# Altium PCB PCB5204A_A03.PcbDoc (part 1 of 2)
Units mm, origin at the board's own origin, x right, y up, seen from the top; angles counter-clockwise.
Board outline 38.5 x 55.5 mm, 4 copper layers (Top Layer, Signal Layer 2, Signal Layer 3, Bottom Layer), stack 1.6 mm thick; 164 components, 105 nets, 579 pads, 390 vias.
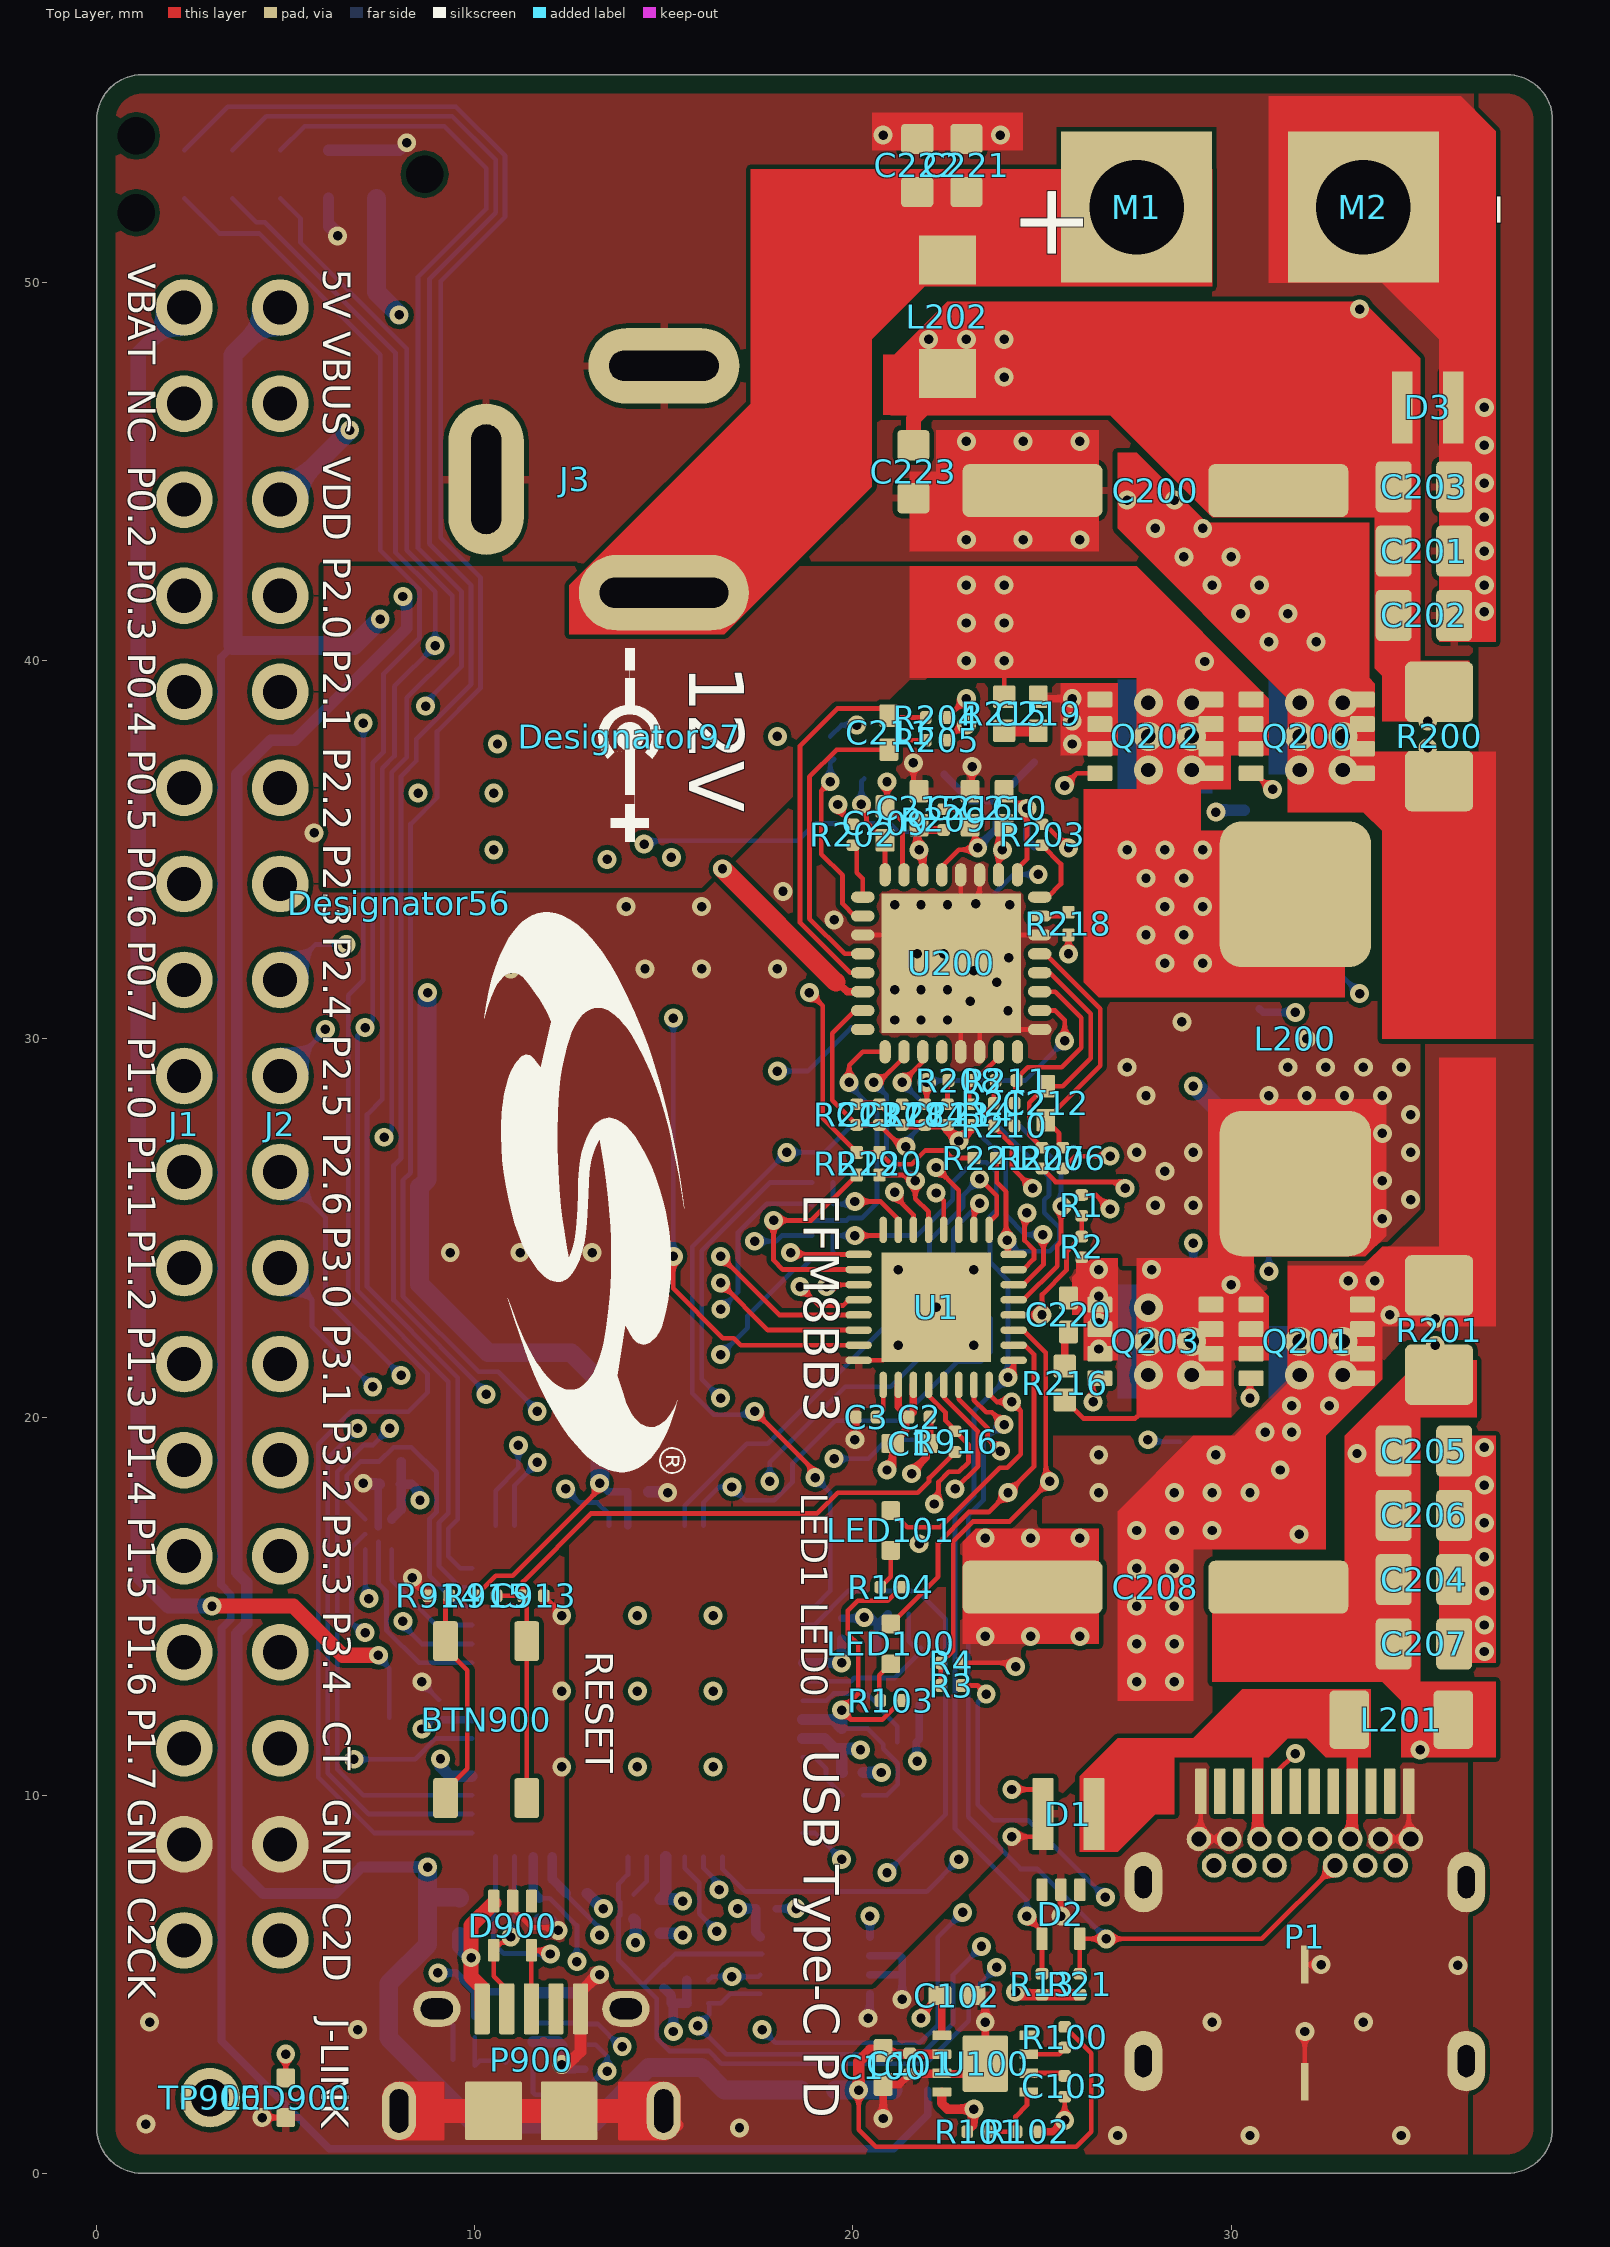
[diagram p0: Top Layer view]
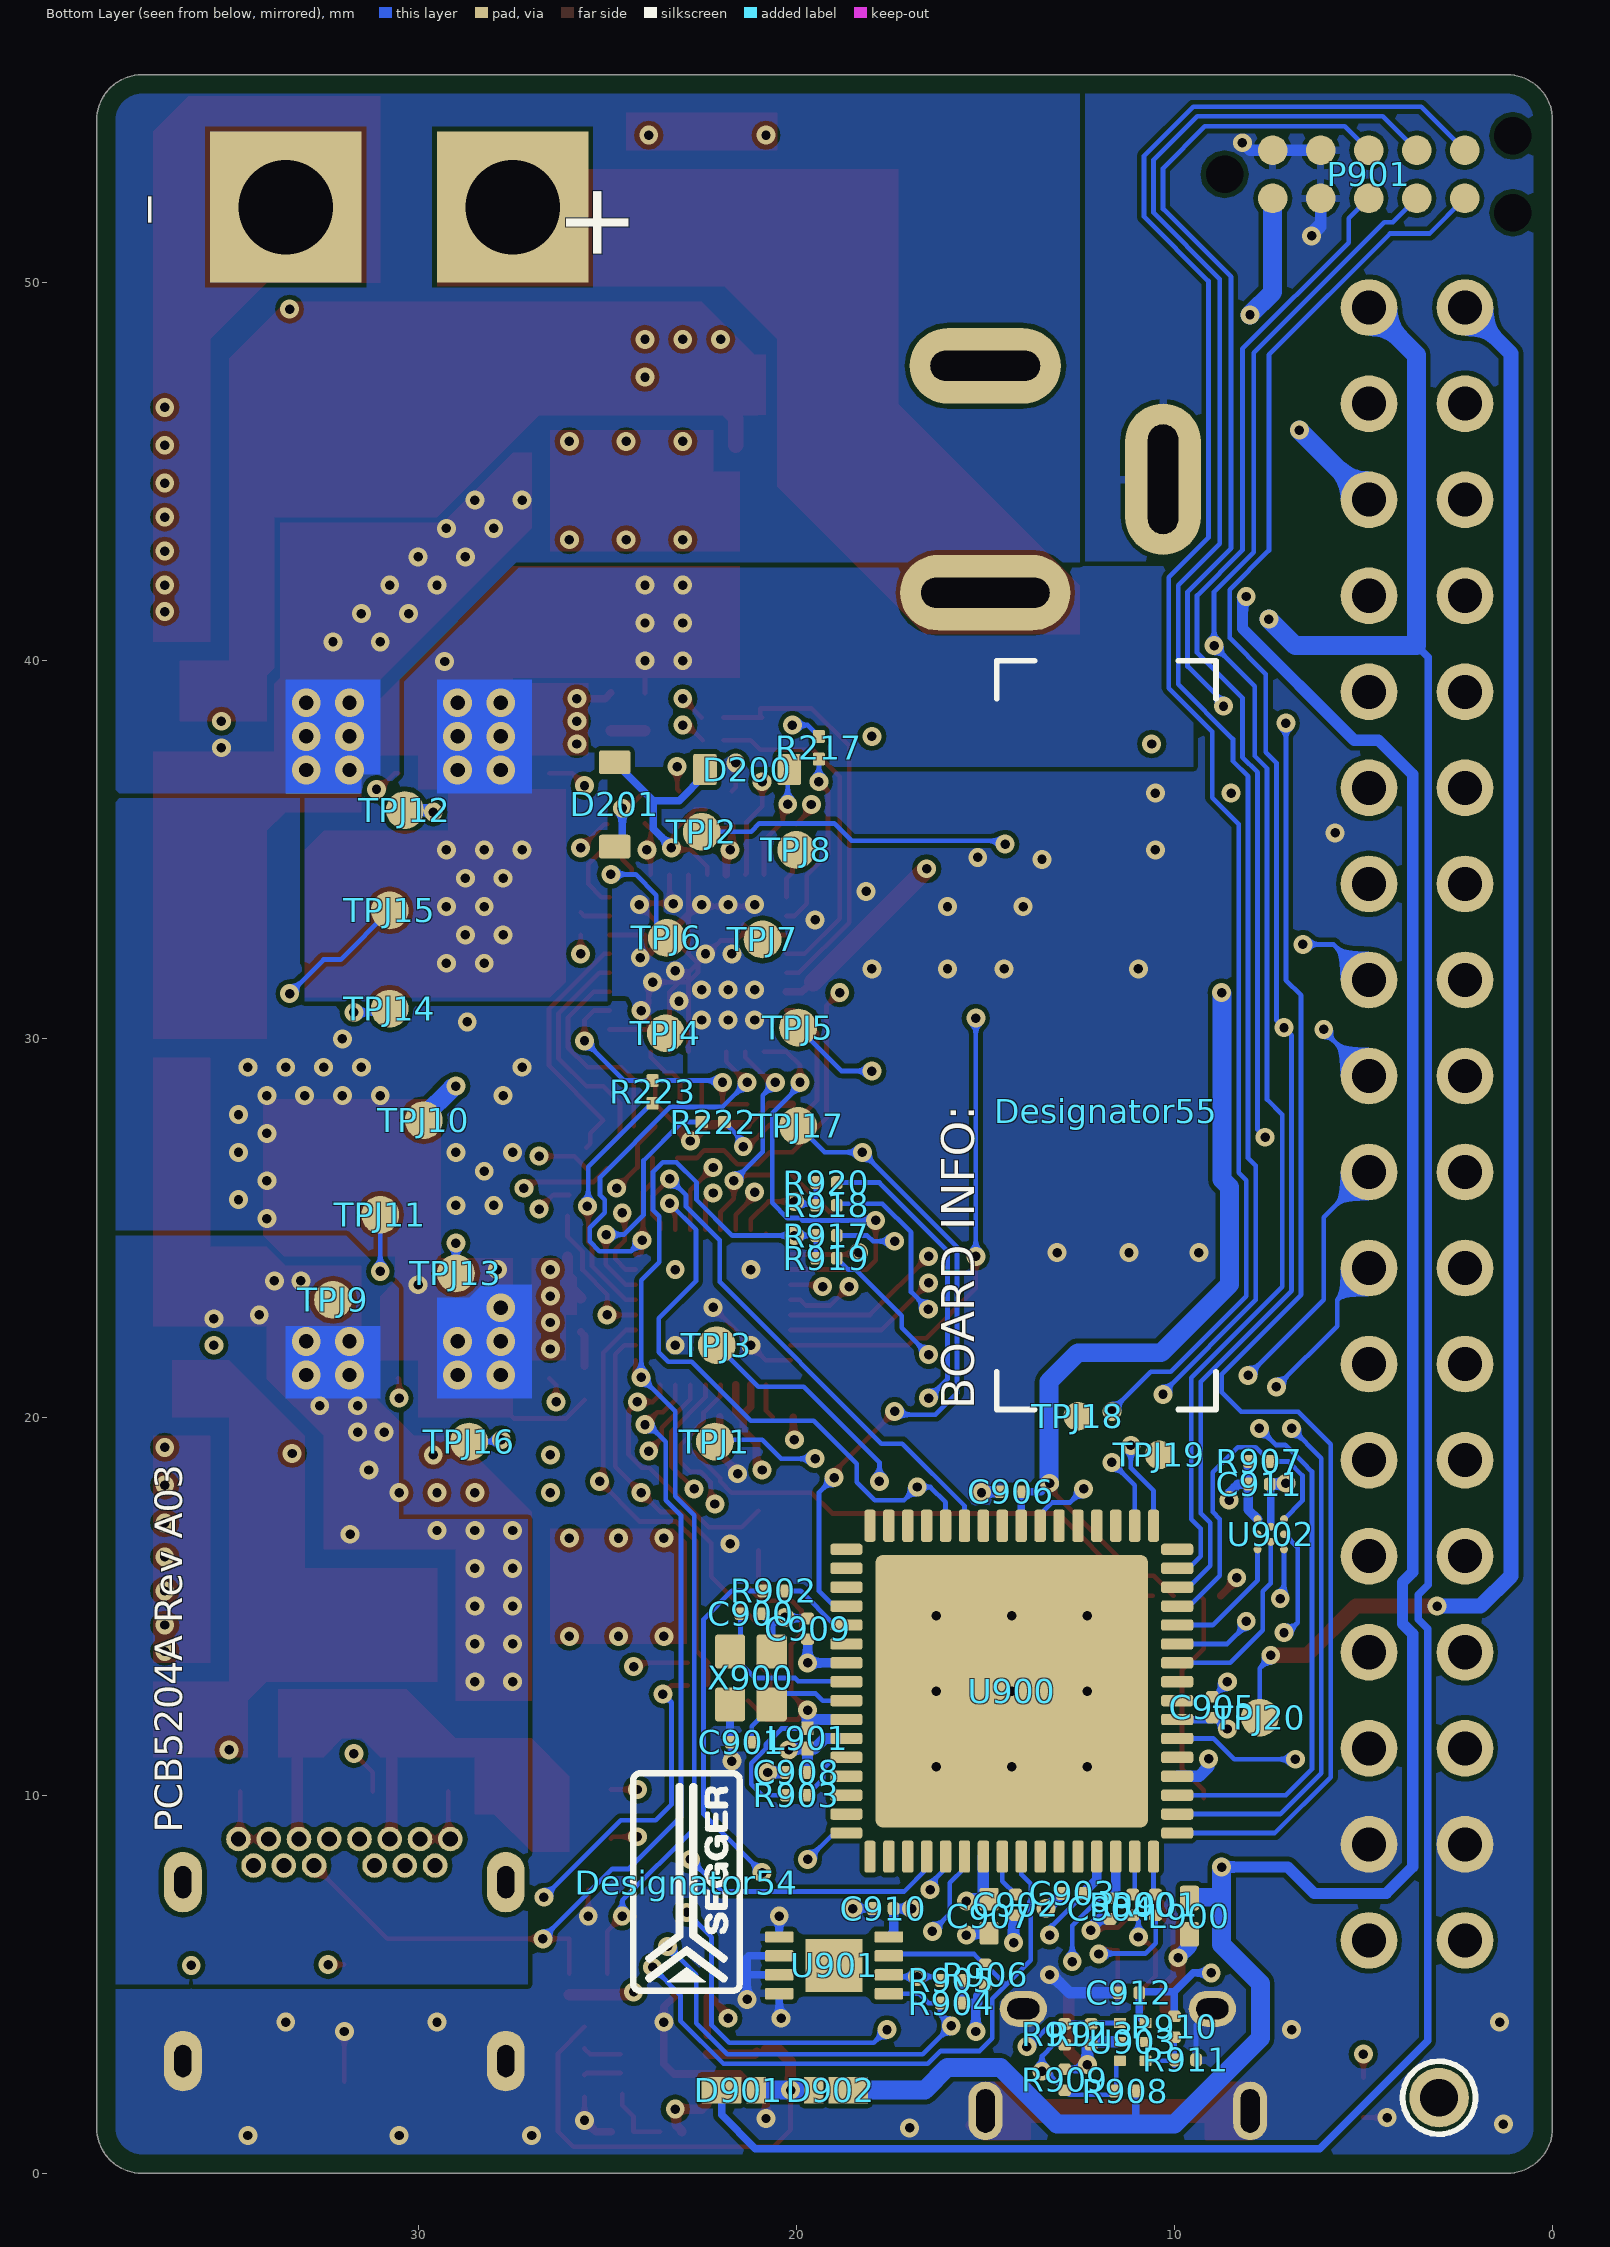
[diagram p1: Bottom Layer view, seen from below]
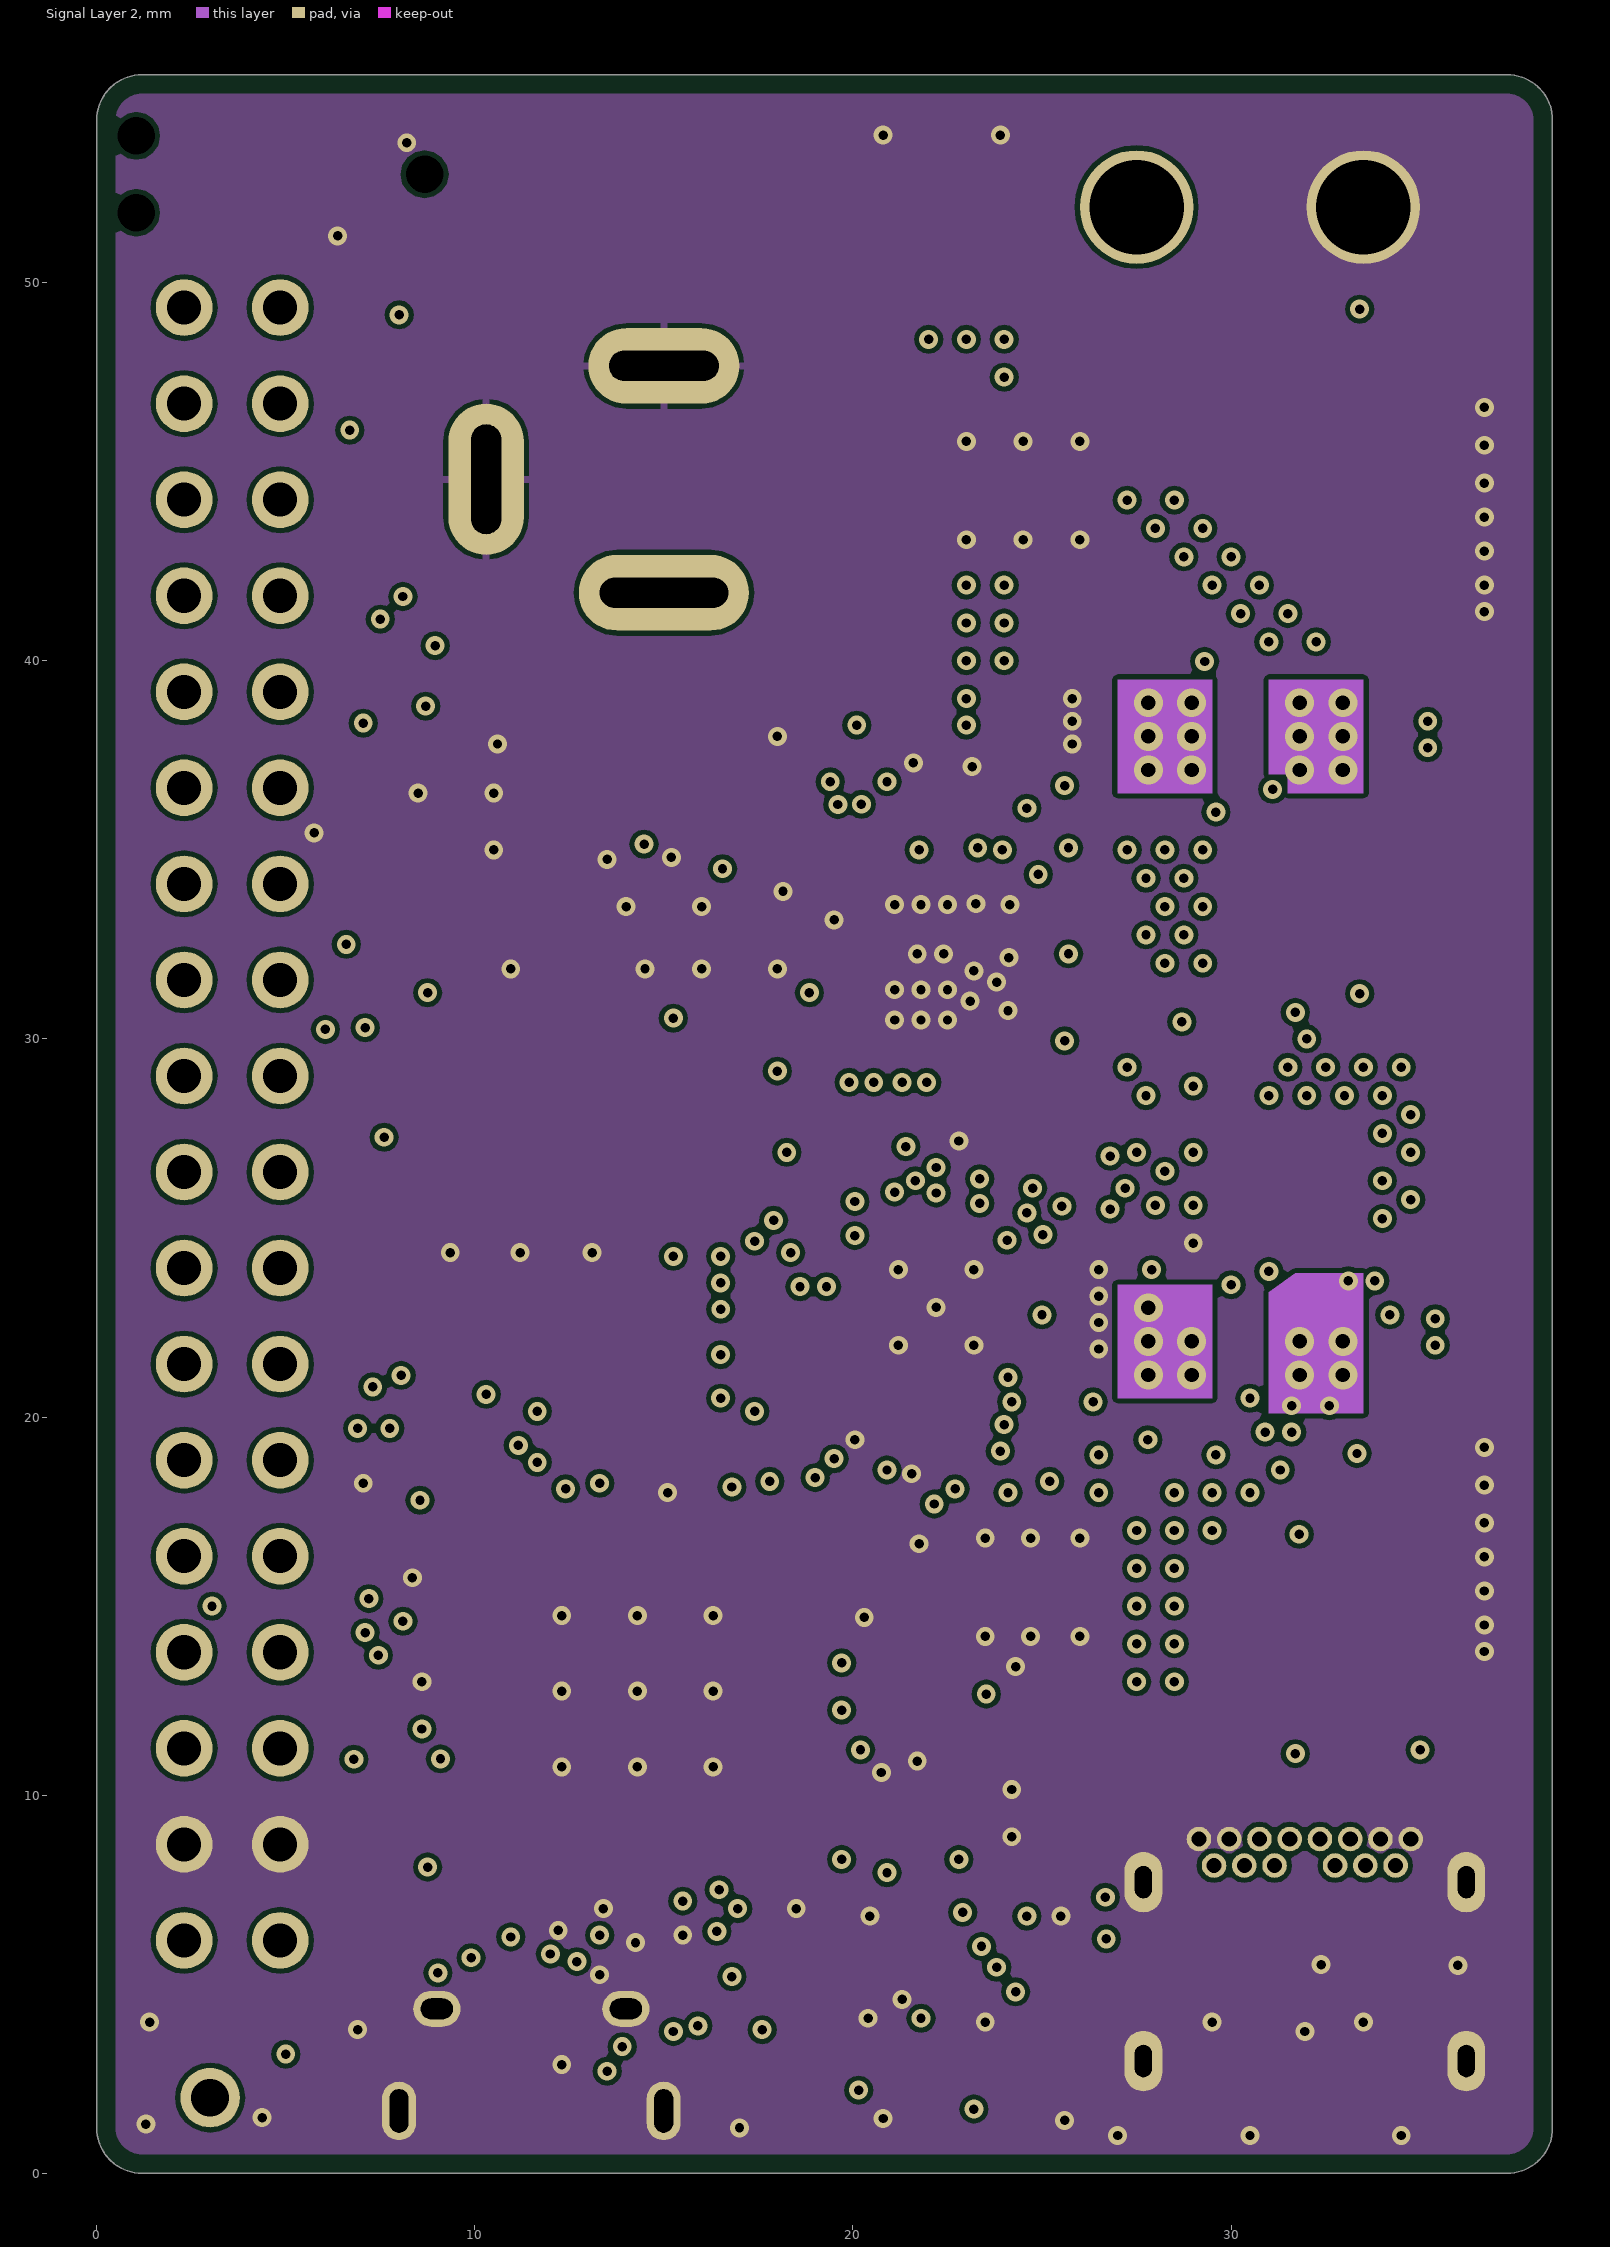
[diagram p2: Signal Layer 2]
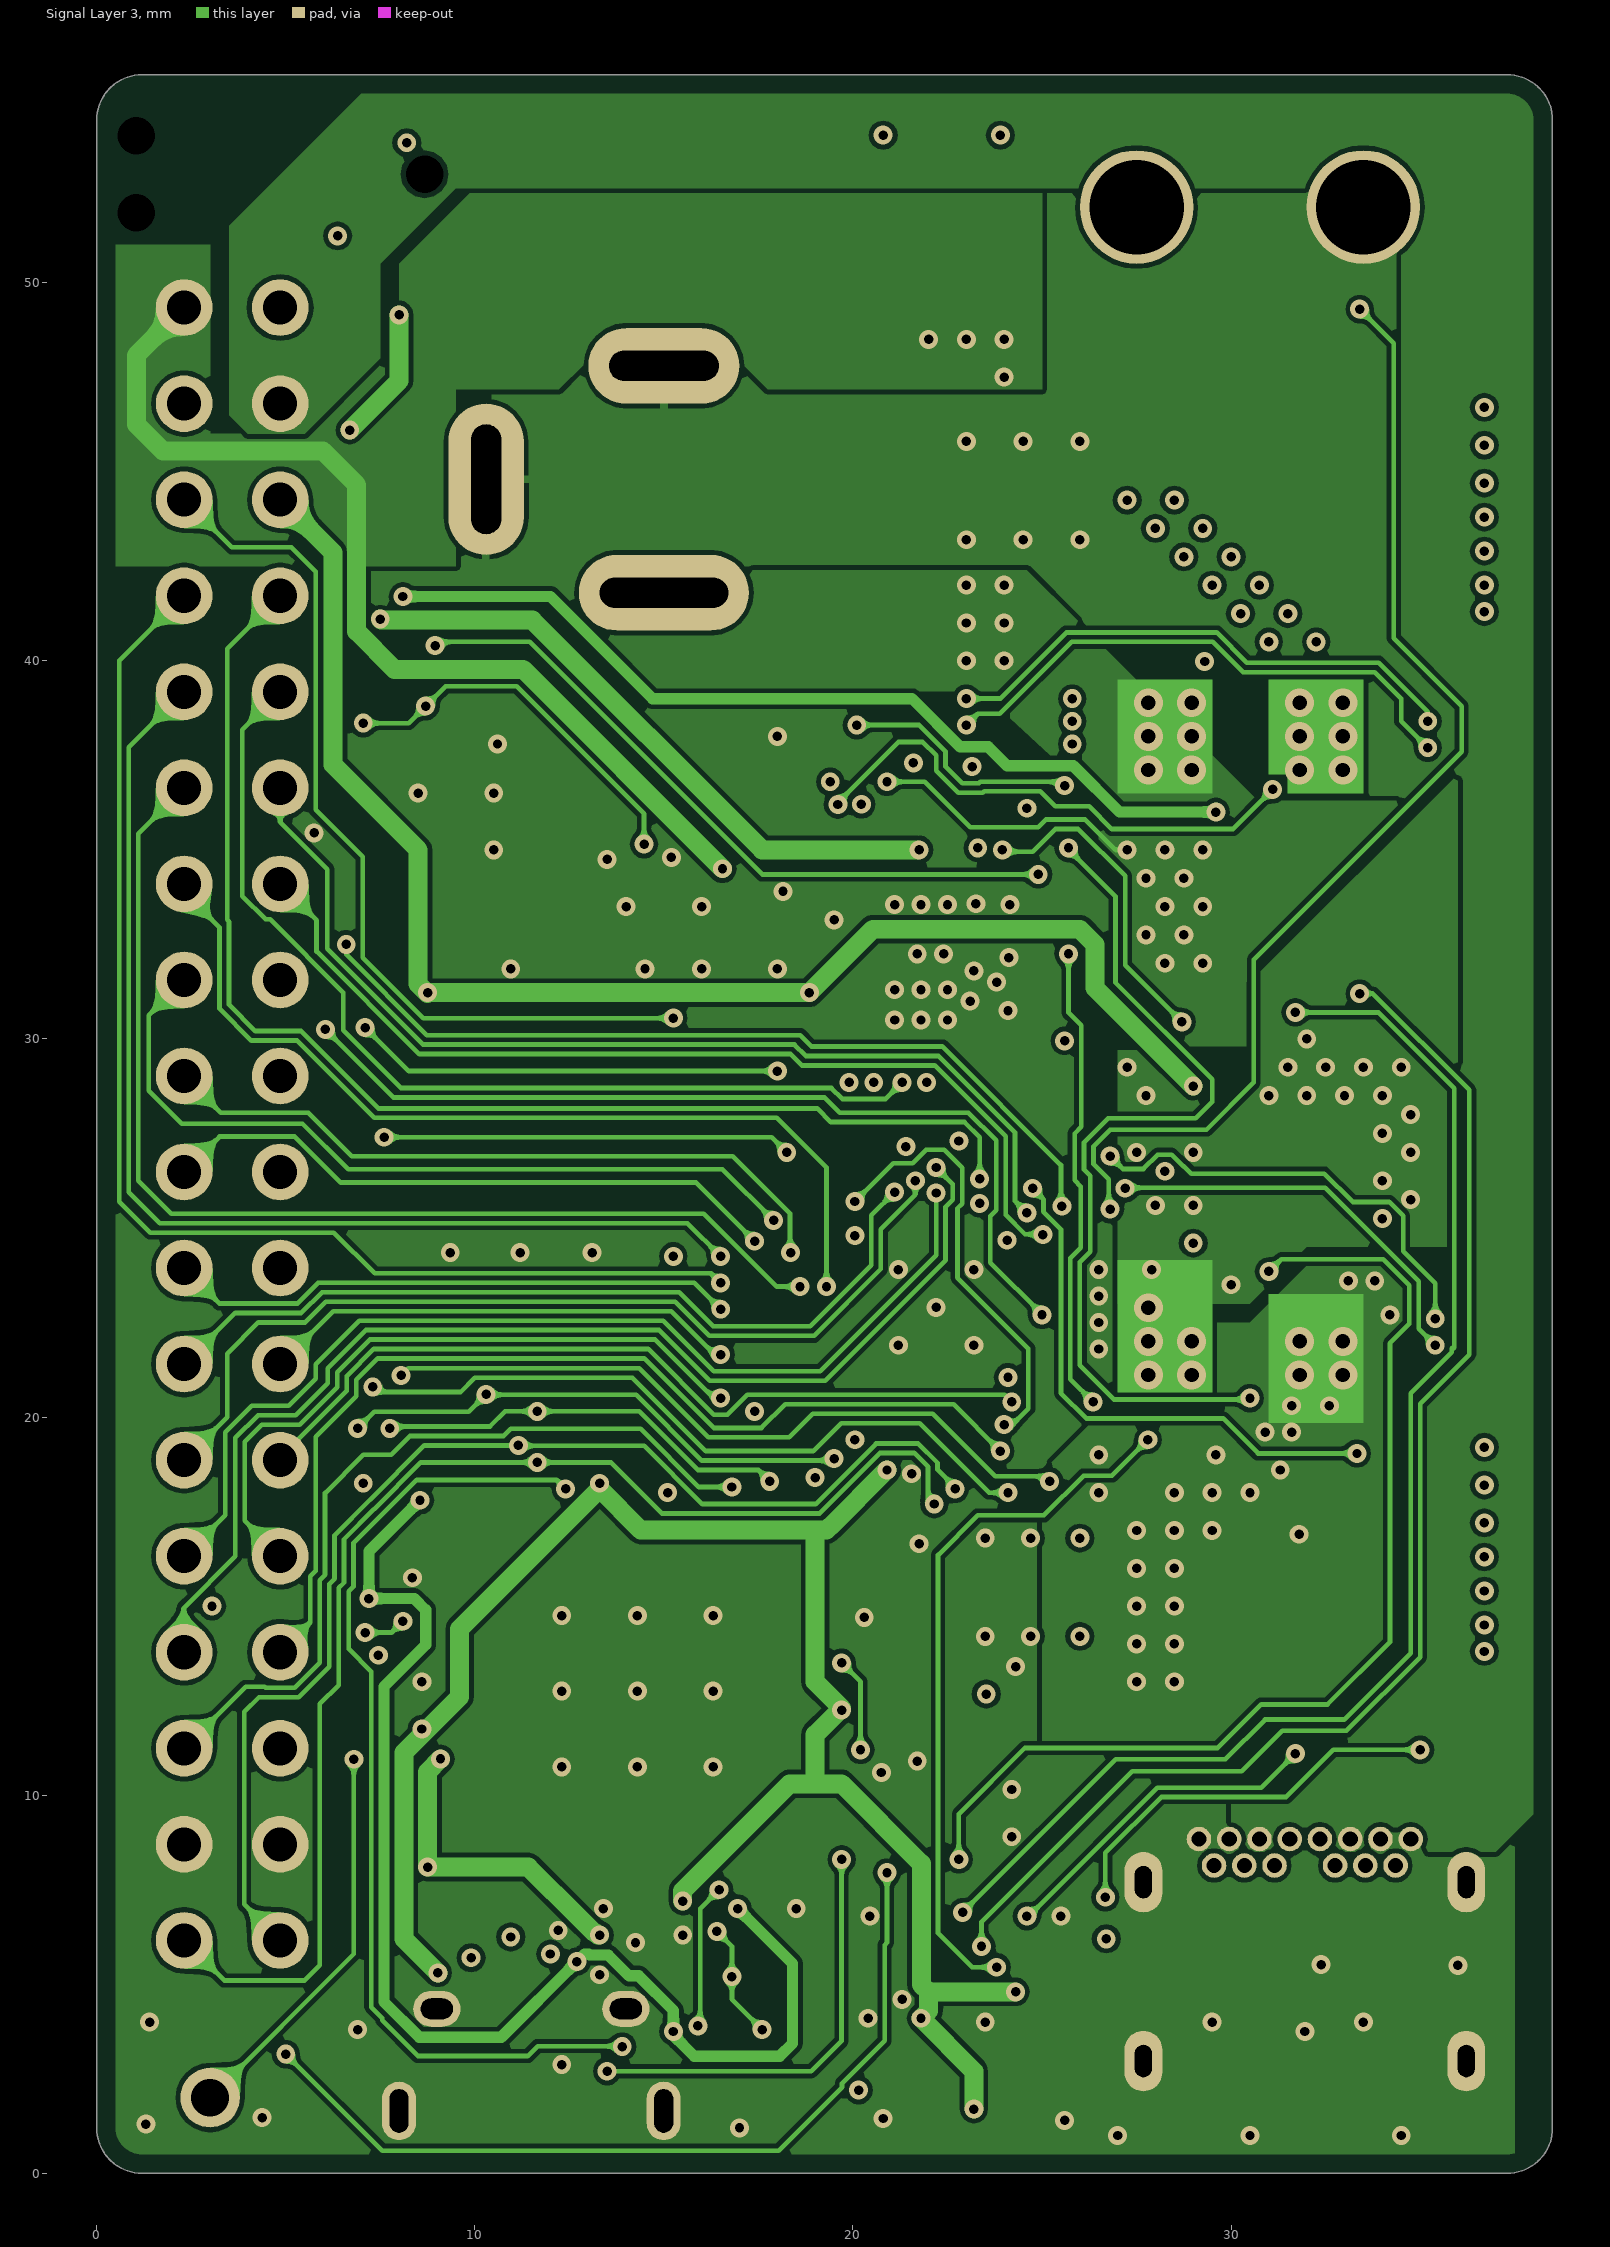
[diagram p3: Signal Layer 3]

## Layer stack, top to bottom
Top Solder: solder mask 0.0102, Solder Resist, Dk 3.5
Top Layer: signal copper 0.035
Dielectric 1: core 0.325, FR-4, Dk 4.2
Signal Layer 2: signal copper 0.018
Dielectric 3: prepreg 0.844, Dk 4.2
Signal Layer 3: signal copper 0.018
Dielectric 2: core 0.325, Dk 4.2
Bottom Layer: signal copper 0.035
Bottom Solder: solder mask 0.0102, Solder Resist, Dk 3.5

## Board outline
0,1.2 0,54.3 cw(c1.2,54.3) 1.2,55.5 37.3,55.5 cw(c37.3,54.3) 38.5,54.3 38.5,1.2 cw(c37.3,1.2) 37.3,0 1.2,0 cw(c1.2,1.2)

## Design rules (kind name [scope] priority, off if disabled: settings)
AcuteAngle [All] p1: minimum=6.00000000000000E+0001 checktracksonly=FALSE
BoardOutlineClearance [All] p1: gap=0.5 ignorepadtopadclearanceinfootprint=FALSE
Clearance Nettie [InComponent('NT*')] p1: gap=0 ignorepadtopadclearanceinfootprint=FALSE
Clearance "Polygon Withdrawal from Board Edge" [(InPolygon) vs (OnLayer('Keep-Out Layer'))] p2: gap=0.635 ignorepadtopadclearanceinfootprint=FALSE except(0: Arc-Hole Track-Hole SMDPad-Hole THPad-Hole Via-Hole Fill-Hole Poly-Hole Region-Hole Text-Hole)
Clearance Clerance_Polygon_VDD_L3 [InNamedPolygon('GND_L3')] p3: gap=0.127 ignorepadtopadclearanceinfootprint=FALSE except(0: Arc-Hole Track-Hole SMDPad-Hole THPad-Hole Via-Hole Fill-Hole Poly-Hole Region-Hole Text-Hole)
Clearance Clerance_Polygon_VBAT_L4 [InNamedPolygon('VBAT_L4')] p4: gap=0.127 ignorepadtopadclearanceinfootprint=FALSE except(0: Arc-Hole Track-Hole SMDPad-Hole THPad-Hole Via-Hole Fill-Hole Poly-Hole Region-Hole Text-Hole)
Clearance Clerance_Polygon_5v_L3 [InNamedPolygon('5V_L3')] p5: gap=0.127 ignorepadtopadclearanceinfootprint=FALSE except(0: Arc-Hole Track-Hole SMDPad-Hole THPad-Hole Via-Hole Fill-Hole Poly-Hole Region-Hole Text-Hole)
Clearance Clerance_Polygon_USBC_VBUS_L4 [InNamedPolygon('USBC_VBUS_L4')] p6: gap=0.127 ignorepadtopadclearanceinfootprint=FALSE except(0: Arc-Hole Track-Hole SMDPad-Hole THPad-Hole Via-Hole Fill-Hole Poly-Hole Region-Hole Text-Hole)
Clearance Clerance_Polygon_GND_L2 [InNamedPolygon('GND_L2')] p7: gap=0.127 ignorepadtopadclearanceinfootprint=FALSE except(0: Arc-Hole Track-Hole SMDPad-Hole THPad-Hole Via-Hole Fill-Hole Poly-Hole Region-Hole Text-Hole)
Clearance Clerance_Polygon_GND_L1 [InNamedPolygon('GND_L1')] p8: gap=0.127 ignorepadtopadclearanceinfootprint=FALSE except(0: Arc-Hole Track-Hole SMDPad-Hole THPad-Hole Via-Hole Fill-Hole Poly-Hole Region-Hole Text-Hole)
Clearance Clerance_Polygon_GND:L4 [InNamedPolygon('GND_L4')] p9: gap=0.127 ignorepadtopadclearanceinfootprint=FALSE except(0: Arc-Hole Track-Hole SMDPad-Hole THPad-Hole Via-Hole Fill-Hole Poly-Hole Region-Hole Text-Hole)
Clearance Clearance_General [All] p10: gap=0.125 ignorepadtopadclearanceinfootprint=FALSE except(0: Arc-Hole Track-Hole SMDPad-Hole THPad-Hole Via-Hole Fill-Hole Poly-Hole Region-Hole Text-Hole)
ComponentClearance ComponentClearance_1 [InComponent('NT*')or InComponent('Desig*')] p1: gap=0 collisioncheckmode=3 verticalgap=0 showdistances=FALSE
ComponentClearance [All] p2: gap=0.2 collisioncheckmode=3 verticalgap=0.254 showdistances=FALSE
HoleSize [All] p1: absolutevalues=TRUE maxlimit=10 minlimit=0.025 maxpercent=80.000 minpercent=20.000
HoleToHoleClearance HoleToHoleClearance_ANT1toPAD [Incomponent ('ANT1') vs ISpad] p1: gap=0 allowstackedmicrovias=TRUE
HoleToHoleClearance HoleToHoleClearance_R1toR2_1 [Incomponent ('R1') vs Incomponent ('R2')] p2: gap=0 allowstackedmicrovias=TRUE
HoleToHoleClearance HoleToHoleClearance_U1toVIA_1 [InComponent ('U1') vs IsVia] p3: gap=0 allowstackedmicrovias=TRUE
HoleToHoleClearance [All] p4: gap=0.254 allowstackedmicrovias=TRUE
MinimumSolderMaskSliver [All] p1: minsoldermaskwidth=0.102
PolygonConnect Polygon_VIA_Connect [IsVia] p1: connectstyle=Direct reliefconductorwidth=0.254 reliefentries=4 polygonreliefangle="90 Angle" airgapwidth=0.254
PolygonConnect PolygonConnect_P900 [InComponent('P900')] p2: connectstyle=Direct reliefconductorwidth=0.254 reliefentries=4 polygonreliefangle="90 Angle" airgapwidth=0.127
PolygonConnect PolygonConnect_P1 [InComponent('P1')] p3: connectstyle=Direct reliefconductorwidth=0.254 reliefentries=4 polygonreliefangle="90 Angle" airgapwidth=0.127
PolygonConnect PolygonConnect_J1_J2 [InComponent('J1') or InComponent('J2') or InComponent('P2') or InComponent('c10') or  InComponent('M1') or InComponent('M2')] p4: connectstyle=Direct reliefconductorwidth=0.305 reliefentries=4 polygonreliefangle="90 Angle" airgapwidth=0.127
PolygonConnect PolygonConnect_U200 [InComponent('U200')] p5: connectstyle=Direct reliefconductorwidth=0.254 reliefentries=4 polygonreliefangle="90 Angle" airgapwidth=0.127
PolygonConnect PolygonConnect_General [All] p6: connectstyle=Relief reliefconductorwidth=0.2 reliefentries=4 polygonreliefangle="90 Angle" airgapwidth=0.12
RoutingTopology [InNet('VIN')] p1: topology=Starburst
RoutingVias [All] p1: holewidth=0.25 width=0.5 viastyle="Through Hole" minholewidth=0.25 minwidth=0.5 maxholewidth=1 maxwidth=1.5
SilkToSilkClearance [All] p1: silktosilkclearance=0.102
SilkToSolderMaskClearance [IsPad] p1: minsilkscreentomaskgap=0.102 clearancetoexposedcopper=TRUE
SolderMaskExpansion [All] p1: expansion=0.051
Width [All] p1: maxlimit=5.08 minlimit=0.1 preferedwidth=0.1
23 further rules are at their usual default settings.

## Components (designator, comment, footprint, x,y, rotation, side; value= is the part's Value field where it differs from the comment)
BTN900 "PTS810" SWITCH_CK_PTS810 10.3,12 r270 top
C1 "10U" C0402_L 21.5,19.3 r0 top
C2 "100N" C0201_L 21.75,20 r0 top
C3 "100N" C0201_L 20.35,20 r180 top
C100 "4U7" C0402_L 20.8,2.8 r270 top
C101 "100N" C0201_L 21.5,2.9 r270 top
C102 "10U" C0402_L 22.75,4.7 r0 top
C103 "33N" C0201_L 25.6,2.3 r270 top
C200 "100U" CAP_NICHICON_RHS_8X8 28,44.5 r0 top locked
C201 "10U" C0805_L 35.1,42.9 r0 top
C202 "10U" C0805_L 35.1,41.2 r0 top
C203 "10U" C0805_L 35.1,44.6 r0 top
C204 "10U" C0805_L 35.1,15.7 r0 top
C205 "10U" C0805_L 35.1,19.1 r0 top
C206 "10U" C0805_L 35.1,17.4 r0 top
C207 "10U" C0805_L 35.1,14 r0 top
C208 "100U" CAP_NICHICON_RHS_8X8 28,15.5 r0 top locked
C209 "100N" C0402_L 20.85,35.7 r270 top
C210 "100N" C0402_L 24,36.1 r90 top
C211 "10N" C0402_L 20.95,38.1 r270 top
C212 "10N" C0402_L 25.1,28.3 r90 top
C213 "1N5" C0201_L 22.5,28 r270 top
C214 "10P" C0201_L 23.1,28 r270 top
C215 "4U7" C0402_L 21.75,36.1 r270 top
C216 "4U7" C0402_L 23.1,36.1 r270 top
C217 "1N" C0201_L 20.7,28 r90 top
C218 "1N" C0201_L 21.3,28 r270 top
C219 "C0402" C0402_L 24.9,38.6 r90 top
C220 "C0402" C0402_L 25.7,22.7 r90 top
C221 "4U7" C0603_L 23,53.1 r90 top
C222 "4U7" C0603_L 21.7,53.1 r90 top
C223 "4U7" C0603_L 21.6,45 r270 top
C900 "10P" C0201_L 21.2,14.8 r180 bottom
C901 "10P" C0201_L 21.45,11.4 r0 bottom
C902 "1U" C0201_L 14.2,7.1 r270 bottom
C903 "100N" C0201_L 12.7,7.4 r0 bottom
C904 "1U" C0201_L 11.7,7 r270 bottom
C905 "100N" C0201_L 9,12.325 r90 bottom
C906 "100N" C0201_L 14.325,18.025 r0 bottom
C907 "4U7" C0402_L 14.9,6.8 r270 bottom
C908 "1U" C0201_L 20,10.6 r0 bottom
C909 "10N" C0201_L 19.7,14.4 r90 bottom
C910 "100N" C0201_L 17.7,7 r0 bottom
C911 "100N" C0201_L 7.75,18.225 r180 bottom
C912 "100N" C0201_L 11.2,4.775 r0 bottom
C913 "100N" C0201_L 11.55,15.275 r0 top
D1 "D26V0H1U2LP20" DFN2020-2_2.0x2.0_DIODES 25.7,9.5 r180 top
D2 "SP1001-04" SOT553_L 25.5,6.85 r270 top
D3 "D26V0H1U2LP20" DFN2020-2_2.0x2.0_DIODES 35.2,46.7 r0 top
D200 "NSR0240H" SOD323_2.5x1.25 21.3,37.125 r0 bottom
D201 "NSR0240H" SOD323_2.5x1.25 24.8,36.2 r90 bottom
D900 "SP1001-04" SOT553_L 11,6.55 r270 top
D901 "NSR20F20" DSN2_1.6X0.8 21.7,2.2 r0 bottom
D902 "NSR20F20" DSN2_1.6X0.8 18.9,2.2 r180 bottom
Designator54 "Comment" Logo_Segger_6x3 22.9,7.7 r90 bottom
Designator55 "Comment" PCB_info_16x6mm 11.8,28.1 r90 bottom
Designator56 "Comment" "Logo_Silabs_regions_15x8mm - copper text" 8,33.6 r270 top locked
Designator57 "Comment" PCB_SPEC_4_LAYER -52.9,139.7 r0 top
Designator97 "Comment" "Logo_DC jack_in_5x1.6mm" 14.1,38 r270 top
J1 "1X18 2.54MM" HDR_M254-1X18_NO_3D 2.313,49.34 r270 top locked
J2 "1X18 2.54MM" HDR_M254-1X18_NO_3D 4.853,49.34 r270 top locked
J3 "PJ-002BH" DC_JACK_CUI_PJ002BH 15,55.5 r180 top locked
L200 "4U2" COIL_WURTH_1050_10.2x10.2 31.7,30 r270 top locked
L201 "FBMJ3216HS480NT" COIL_YUDEN_FBMJ3216_1206 34.5,12 r180 top
L202 "BLM31SN500SN1L" COIL_MURATA_BLM31_1206 22.5,49.1 r270 top
L900 "BLM15AG221SN1D" COIL_MUR_BLM15H_0402_L 9.6,6.8 r90 bottom
L901 "CIM03U241" COIL_0201_L 19.7,11.5 r270 bottom
LED100 "AMBER" LED0402_L 21,14 r270 top
LED101 "AMBER" LED0402_L 21,17 r270 top
LED900 "BLUE" LED0402_L 5,2 r90 top
M1 "HOLE_PTH_2.5MM" 2.5MM_PLATED 27.5,52 r180 top
M2 "HOLE_PTH_2.5MM" 2.5MM_PLATED 33.5,52 r180 top
P1 "USB-C RECEPTACLE" WE_632723_USB-C_RCPT 31.95,7.7 r0 top
P900 "USB MICRO-B" AMP_FCI_10118194 11.5,0.2 r0 top
P901 "TC2050-NL" TAG_CONN_TC2050-NL 4.86,52.865 r180 bottom
Q200 "NTTFS4C13N" WDFN8_M065_3.3X3.3_ONSEMI 32,38 r90 top
Q201 "NTTFS4C13N" WDFN8_M065_3.3X3.3_ONSEMI 32,22 r90 top
Q202 "NTTFS4C13N" WDFN8_M065_3.3X3.3_ONSEMI 28,38 r90 top
Q203 "NTTFS4C06N" WDFN8_M065_3.3X3.3_ONSEMI 28,22 r90 top
R1 "91K" R0201_L#1 26.05,25.6 r270 top
R2 "10K" R0201_L#1 26.05,24.5 r90 top
R3 "91K" R0201_L#1 22.6,12.9 r0 top
R4 "10K" R0201_L#1 22.6,13.5 r180 top
R13 "12K" R0201_L#1 25,5 r270 top
R21 "12K" R0201_L#1 26,5 r270 top
R100 "10K" R0201_L#1 25.6,3.6 r270 top
R101 "180K" R0201_L#1 23.3,1.1 r0 top
R102 "110K" R0201_L#1 24.6,1.1 r0 top
R103 "2K7" R0201_L#1 21,12.5 r0 top
R104 "2K7" R0201_L#1 21,15.5 r0 top
R200 "0R005" R1206_VISHAY_WSL1206 35.5,38 r270 top
R201 "0R005" R1206_VISHAY_WSL1206 35.5,22.3 r270 top
R202 "3R9" R0201_L#1 20,35.4 r90 top
R203 "3R9" R0201_L#1 25,35.4 r90 top
R204 "10R" R0201_L#1 22.2,38.5 r0 top
R205 "10R" R0201_L#1 22.2,37.9 r0 top
R206 "10R" R0201_L#1 25.55,26.85 r270 top
R207 "10R" R0201_L#1 25,26.85 r270 top
R208 "20K5" R0201_L#1 22.8,28.9 r180 top
R209 "1R" R0201_L#1 22.4,35.8 r270 top
R210 "90K9" R0201_L#1 24,27.7 r180 top
R211 "20K" R0201_L#1 24.05,28.9 r0 top
R212 "20K5" R0201_L#1 24,28.3 r0 top
R213 "11K8" R0201_L#1 20.1,28 r270 top
R214 "24K3" R0201_L#1 21.9,28 r90 top
R215 "VALUE?" R0402_L 24,38.6 r90 top
R216 "VALUE?" R0402_L 25.6,20.9 r270 top
R217 "0R" R0201_L#2 19.4,37.7 r90 bottom
R218 "0R" R0201_L#2 25.7,33.05 r270 top
R219 "4K7" R0201_L#2 20.1,26.7 r270 top
R220 "4K7" R0201_L#2 20.7,26.7 r270 top
R221 "4K7" R0201_L#2 23.5,26.85 r0 top
R222 "0R" R0201_L#2 22.2,27.8 r180 bottom
R223 "0R" R0201_L#2 23.8,28.6 r90 bottom
R900 "15R" R0201_L#1 11.1,7.1 r90 bottom
R901 "15R" R0201_L#1 10.5,7.1 r90 bottom
R902 "2K0" R0201_L#1 20.6,15.4 r0 bottom
R903 "1K" R0201_L#1 20,10 r0 bottom
R904 "4K7" R0201_L#1 15.9,4.5 r180 bottom
R905 "4K7" R0201_L#1 15.9,5.1 r180 bottom
R906 "10K" R0201_L#1 15,5.25 r270 bottom
R907 "330K" R0201_L#1 7.75,18.825 r0 bottom
R908 "15K" R0201_L#1 11.3,2.175 r180 bottom
R909 "12K" R0201_L#1 12.9,2.475 r90 bottom
R910 "470K" R0201_L#1 10,3.875 r270 bottom
R911 "470K" R0201_L#1 9.7,3 r180 bottom
R912 "100K" R0201_L#1 12.9,3.675 r90 bottom
R913 "100K" R0201_L#1 12.2,3.675 r270 bottom
R914 "100R" R0201_L#1 9.05,15.275 r0 top
R915 "1K" R0201_L#1 10.3,15.275 r0 top
R916 "1K" R0201_L#1 22.7,19.35 r270 top
R917 "0R" R0201_L#1 19.2,24.8 r0 bottom
R918 "0R" R0201_L#1 19.2,25.6 r0 bottom
R919 "0R" R0201_L#1 19.2,24.2 r0 bottom
R920 "0R" R0201_L#1 19.2,26.2 r0 bottom
TP900 "PROTO_TH" PROTO_TH 3,2 r90 top
TPJ1 "TPJ_SMD" TP_1.0_SMD#1 22.15,19.35 r90 bottom locked
TPJ2 "TPJ_SMD" TP_1.0_SMD#1 22.5,35.48 r90 bottom locked
TPJ3 "TPJ_SMD" TP_1.0_SMD#1 22.1,21.9 r90 bottom locked
TPJ4 "TPJ_SMD" TP_1.0_SMD#1 23.45,30.15 r90 bottom locked
TPJ5 "TPJ_SMD" TP_1.0_SMD#1 19.95,30.3 r90 bottom locked
TPJ6 "TPJ_SMD" TP_1.0_SMD#1 23.42,32.67 r90 bottom locked
TPJ7 "TPJ_SMD" TP_1.0_SMD#1 20.89,32.63 r90 bottom locked
TPJ8 "TPJ_SMD" TP_1.0_SMD#1 20,35 r90 bottom locked
TPJ9 "TPJ_SMD" TP_1.0_SMD#1 32.25,23.1 r90 bottom locked
TPJ10 "TPJ_SMD" TP_1.0_SMD#1 29.85,27.85 r90 bottom locked
TPJ11 "TPJ_SMD" TP_1.0_SMD#1 31,25.35 r90 bottom locked
TPJ12 "TPJ_SMD" TP_1.0_SMD#1 30.35,36.05 r90 bottom
TPJ13 "TPJ_SMD" TP_1.0_SMD#1 29,23.8 r90 bottom locked
TPJ14 "TPJ_SMD" TP_1.0_SMD#1 30.75,30.8 r90 bottom locked
TPJ15 "TPJ_SMD" TP_1.0_SMD#1 30.75,33.4 r90 bottom locked
TPJ16 "TPJ_SMD" TP_1.0_SMD#1 28.65,19.35 r90 bottom locked
TPJ17 "TPJ_SMD" TP_1.0_SMD#1 19.95,27.7 r90 bottom locked
TPJ18 "TPJ_SMD" TP_1.0_SMD#2 12.55,20.02 r90 bottom locked
TPJ19 "TPJ_SMD" TP_1.0_SMD#2 10.4,19 r90 bottom locked
TPJ20 "TPJ_SMD" TP_1.0_SMD#1 7.74,12.05 r90 bottom locked
U1 "EFM8BB31F64" QFN32_M040_4.0X4.0_EP_SL 22.2,22.9 r90 top
U100 "LP3982ILD-ADJ" WSON8_M050_2.5X3.0_HEAT 23.5,2.9 r0 top
U200 "NCP81239" QFN32_M050_5x5_ON 22.6,32 r0 top locked
U900 "EFM32GG330F1024" QFN64_M050_SQ_9.0_SQ_EP 14.3,12.75 r270 bottom locked
U901 "24AA024" TDFN8_M050_2.0X3.0_EP 19,5.5 r180 bottom
U902 "MX25R8035F" BGA8_M040_1.24x1.75_WLCSP 7.45,16.9 r180 bottom
U903 "NCX2200" SOT886 11.1,3.475 r180 bottom
X900 "48 MHz" X_SSS_DSX211SH_2.05X1.65-4 21.2,13.1 r90 bottom

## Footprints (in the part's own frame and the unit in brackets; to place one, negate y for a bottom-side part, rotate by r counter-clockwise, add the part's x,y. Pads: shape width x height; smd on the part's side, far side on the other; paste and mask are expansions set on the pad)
2.5MM_PLATED [mm] "2.5MM_PLATED"
  rect 4x4 / inner round 3 / far side rect 4x4 hole 2.5: 1(0,0)
AMP_FCI_10118194 [mm] "Amphenol FCI, 10118194-000XLF, Micro USB Type B"
  rrect20% 0.4x1.35 smd mask+0.076: 1(-1.305,4.15) 2(-0.655,4.15) 3(-0.005,4.15) 4(0.645,4.15) 5(1.295,4.15)
  oval 1.25x0.95 hole 0.55 slot 0.85 at 0 deg: 6(-2.505,4.15) 7(2.495,4.15)
  oval 0.9x1.55 hole 0.5 slot 1.15 at 90 deg paste+0: 8(-3.505,1.45) 9(3.495,1.45)
  rrect5% 1.5x1.55 smd: 10(-1.005,1.45) 11(0.995,1.45)
  Top Layer region: -3.501,0.676 -2.33,0.676 -2.306,0.7 -2.308,2.206 -2.33,2.228 -3.497,2.228 -3.587,2.228 -3.754,2.159 -3.881,2.031 -3.95,1.865 -3.95,1.775 -3.95,1.775 -3.95,1.125 -3.95,1.036 -3.882,0.871 -3.755,0.744 -3.59,0.676 -3.501,0.676
  Top Layer region: 3.476,0.676 2.32,0.676 2.296,0.7 2.298,2.206 2.32,2.228 3.472,2.228 3.567,2.228 3.743,2.155 3.877,2.021 3.95,1.845 3.95,1.75 3.95,1.75 3.95,1.15 3.95,1.056 3.878,0.882 3.744,0.748 3.57,0.676 3.476,0.676
  body extent -4.05,-1.18 4,4.4, height 3.12
BGA8_M040_1.24x1.75_WLCSP [mm] "BGA, 8 pin. U100"
  round 0.21 smd mask+0.051: A1(-0.35,0.4) A3(0.35,0.4) B2(0,0.2) C1(-0.35,0) C3(0.35,0) D2(0,-0.2) E1(-0.35,-0.4) E3(0.35,-0.4)
  body extent -0.63,-0.89 0.63,0.88, height 0.52
C0201_L [mm] "Capacitor, Chip; 0.60 mm L X 0.30 mm W X 0.33 mm H body"
  rrect52% 0.31x0.34 smd: 1(-0.275,0) 2(0.275,0)
  body extent -0.3,-0.15 0.3,0.15, height 0.3
C0402_L [mm] "Chip Capacitor, 2-Leads, Body 1.0x0.5mm, IPC High Density"
  rrect20% 0.6x0.5 smd mask+0.051: 1(-0.45,0) 2(0.45,0)
  body extent -0.5,-0.25 0.5,0.25, height 0.6
C0603_L [mm] "Capacitor, 0603, High Density (C)"
  rrect25% 0.8x0.85 smd: 1(-0.7,0) 2(0.7,0)
  body extent -0.88,-0.48 0.87,0.48, height 0.95
C0805_L [mm] "Capacitor, 0805"
  rrect25% 0.95x1.35 smd: 1(-0.8,0) 2(0.8,0)
  body extent -1.1,-0.72 1.1,0.72, height 1.45
CAP_NICHICON_RHS_8X8 [mm] "nichon RHS1V101MCN1GS"
  rrect25% 3.7x1.4 smd: 1(3.25,0) 2(-3.25,0)
  body extent -4.2,-4.2 4.2,4.2, height 10
COIL_0201_L [mm] "Inductor, 0201, High Density (C)"
  rrect10% 0.37x0.32 smd: 1(-0.27,0) 2(0.27,0)
  body extent -0.32,-0.17 0.32,0.17, height 0.33
COIL_MUR_BLM15H_0402_L [mm] "Chip Inductor Murata BLM15H, High Density (C)"
  rrect25% 0.65x0.5 smd: 1(-0.48,0) 2(0.48,0)
  body extent -0.53,-0.28 0.53,0.28, height 0.26
COIL_MURATA_BLM31_1206 [mm] "COIL_MURATA_BLM31_1206"
  rect 1.3x1.5 smd: 1(-1.5,0) 2(1.5,0)
  Top Layer region: 1,-1.7 2.6,-1.7 2.6,1.7 1,1.7
  Top Layer region: -2.6,-1.7 -1,-1.7 -1,1.7 -2.6,1.7
  body extent -1.6,-0.8 1.6,0.8, height 1.45
COIL_WURTH_1050_10.2x10.2 [mm] "wurth 744325420"
  rrect30% 3.85x4 smd mask+0.051: 1(-3.825,0) 2(3.825,0)
  body extent -5.1,-5.1 5.1,5.1, height 1.5
COIL_YUDEN_FBMJ3216_1206 [mm] "Taiyo Yuden FBMJ3216HS480NT"
  rrect25% 1.05x1.55 smd paste-0.05: 1(-1.375,0) 2(1.375,0)
  body extent -1.6,-0.8 1.6,0.8, height 1
DC_JACK_CUI_PJ002BH [mm] "DC JACK, CUI PJ-002BH 2.5 mm H: 11.0 (171009)"
  oval 4.5x2 hole 0.8 slot 3.4 at 0 deg: 1(0,13.7)
  oval 4x2 hole 0.8 slot 2.9 at 0 deg: 2(0,7.7)
  oval 2x4 hole 0.8 slot 2.9 at 90 deg: 3(4.7,10.7)
  body extent -4.5,-0.02 4.9,14.38, height 11
DFN2020-2_2.0x2.0_DIODES [mm] "D26V0H1U2LP20"
  rrect5% 0.55x1.9 smd paste+0 mask+0.05: 1(-0.675,0) 2(0.675,0)
  body extent -1,-1 1,1, height 1.15
DSN2_1.6X0.8 [mm] "Diode 0603 DSN2 CASE152AB H: 0.28 On-Semi (170126)"
  rrect5% 0.52x0.7 smd mask+0.05: 1(-0.64,0)
  rrect5% 1.05x0.7 smd mask+0.05: 2(0.275,0)
  body extent -0.8,-0.4 0.8,0.4, height 0.31
HDR_M254-1X18_NO_3D [mm] "Header 2.54 (170130)"
  round 1.5 hole 0.9: 1(0,0) 2(2.54,0) 3(5.08,0) 4(7.62,0) 5(10.16,0) 6(12.7,0) 7(15.24,0) 8(17.78,0) 9(20.32,0) 10(22.86,0) 11(25.4,0) 12(27.94,0) 13(30.48,0) 14(33.02,0) 15(35.56,0) 16(38.1,0) 17(40.64,0) 18(43.18,0)
  body extent -1.44,-1.5 44.63,1.48, height 9.8
LED0402_L [mm] "Led smd 0402"
  rrect25% 0.5x0.5 smd: 1(-0.525,0) 2(0.525,0)
  body extent -0.5,-0.25 0.5,0.25, height 0.3
"Logo_DC jack_in_5x1.6mm" [mm] "Attila created"
  silkscreen extent -2.33,-0.83 2.79,0.83
Logo_Segger_6x3 [mm] "Attila created few segment"
  silkscreen extent -2.95,-1.48 2.96,1.49
"Logo_Silabs_regions_15x8mm - copper text" [mm] "Attila created few segment"
  silkscreen extent 0.25,2.25 15.08,7.55
PCB_info_16x6mm [mm]
  silkscreen extent -7.9,-2.9 11.9,2.9
PCB_SPEC_4_LAYER [mm]
PROTO_TH [mil] "Test Point, 1.0 mm (= TP_1.0_D62)"
  round 62 hole 39.37: 1(0,0)
QFN32_M040_4.0X4.0_EP_SL [mm] "(Silicon Labs EFM8UB4)"
  oval 0.7x0.2 smd: 1(-2.05,1.4) 2(-2.05,1) 3(-2.05,0.6) 4(-2.05,0.2) 5(-2.05,-0.2) 6(-2.05,-0.6) 7(-2.05,-1) 8(-2.05,-1.4) 17(2.05,-1.4) 18(2.05,-1) 19(2.05,-0.6) 20(2.05,-0.2) 21(2.05,0.2) 22(2.05,0.6) 23(2.05,1) 24(2.05,1.4)
  oval 0.2x0.7 smd: 9(-1.4,-2.05) 10(-1,-2.05) 11(-0.6,-2.05) 12(-0.2,-2.05) 13(0.2,-2.05) 14(0.6,-2.05) 15(1,-2.05) 16(1.4,-2.05) 25(1.4,2.05) 26(1,2.05) 27(0.6,2.05) 28(0.2,2.05) 29(-0.2,2.05) 30(-0.6,2.05) 31(-1,2.05) 32(-1.4,2.05)
  rect 2.9x2.9 smd: 33(0,0)
  body extent -2,-2 2,2, height 0.56
QFN32_M050_5x5_ON [mm] "NCP81239"
  oval 0.62x0.3 smd: 1(-2.34,1.75) 2(-2.34,1.25) 3(-2.34,0.75) 4(-2.34,0.25) 5(-2.34,-0.25) 6(-2.34,-0.75) 7(-2.34,-1.25) 8(-2.34,-1.75) 17(2.34,-1.75) 18(2.34,-1.25) 19(2.34,-0.75) 20(2.34,-0.25) 21(2.34,0.25) 22(2.34,0.75) 23(2.34,1.25) 24(2.34,1.75)
  oval 0.3x0.62 smd: 9(-1.75,-2.34) 10(-1.25,-2.34) 11(-0.75,-2.34) 12(-0.25,-2.34) 13(0.25,-2.34) 14(0.75,-2.34) 15(1.25,-2.34) 16(1.75,-2.34) 25(1.75,2.34) 26(1.25,2.34) 27(0.75,2.34) 28(0.25,2.34) 29(-0.25,2.34) 30(-0.75,2.34) 31(-1.25,2.34) 32(-1.75,2.34)
  rect 3.7x3.7 smd paste-10: 33(0,0)
  body extent -2.5,-2.5 2.5,2.5, height 0.56
QFN64_M050_SQ_9.0_SQ_EP [mm] "QFN64, Pitch 0.5 mm, Exposed Pad High Density 9.0X9.0X0.85"
  rrect50% 0.85x0.3 smd paste-0.04 mask+0.06: 1(-4.375,3.75) 16(-4.375,-3.75) 33(4.375,-3.75) 48(4.375,3.75)
  rrect40% 0.85x0.3 smd paste-0.04 mask+0.06: 2(-4.375,3.25) 3(-4.375,2.75) 4(-4.375,2.25) 5(-4.375,1.75) 6(-4.375,1.25) 7(-4.375,0.75) 8(-4.375,0.25) 9(-4.375,-0.25) 10(-4.375,-0.75) 11(-4.375,-1.25) 12(-4.375,-1.75) 13(-4.375,-2.25) 14(-4.375,-2.75) 15(-4.375,-3.25) 34(4.375,-3.25) 35(4.375,-2.75) 36(4.375,-2.25) 37(4.375,-1.75) 38(4.375,-1.25) 39(4.375,-0.75) 40(4.375,-0.25) 41(4.375,0.25) 42(4.375,0.75) 43(4.375,1.25) 44(4.375,1.75) 45(4.375,2.25) 46(4.375,2.75) 47(4.375,3.25)
  rrect50% 0.3x0.85 smd paste-0.04 mask+0.06: 17(-3.75,-4.375) 32(3.75,-4.375) 49(3.75,4.375) 64(-3.75,4.375)
  rrect40% 0.3x0.85 smd paste-0.04 mask+0.06: 18(-3.25,-4.375) 19(-2.75,-4.375) 20(-2.25,-4.375) 21(-1.75,-4.375) 22(-1.25,-4.375) 23(-0.75,-4.375) 24(-0.25,-4.375) 25(0.25,-4.375) 26(0.75,-4.375) 27(1.25,-4.375) 28(1.75,-4.375) 29(2.25,-4.375) 30(2.75,-4.375) 31(3.25,-4.375) 50(3.25,4.375) 51(2.75,4.375) 52(2.25,4.375) 53(1.75,4.375) 54(1.25,4.375) 55(0.75,4.375) 56(0.25,4.375) 57(-0.25,4.375) 58(-0.75,4.375) 59(-1.25,4.375) 60(-1.75,4.375) 61(-2.25,4.375) 62(-2.75,4.375) 63(-3.25,4.375)
  rrect5% 7.2x7.2 smd paste-3.7 mask+0.06: 65(0,0)
  body extent -4.55,-4.55 4.55,4.55, height 0.91
R0201_L#1 [mm] "Resistor, Chip; 0.60 mm L X 0.30 mm W X 0.28 mm H body"
  rrect52% 0.31x0.34 smd: 1(-0.275,0) 2(0.275,0)
  body extent -0.3,-0.15 0.3,0.15, height 0.23
R0201_L#2 [mm] "Resistor (Chip2PinSM127P600-8N)"
  rrect25% 0.34x0.32 smd: 1(-0.3,0) 2(0.3,0)
  body extent -0.32,-0.13 0.32,0.13, height 0.3
R0402_L [mm] "Chip Resistor, 2-Leads, Body 1.0x0.5mm, IPC High Density"
  rrect20% 0.6x0.6 smd mask+0.051: 1(-0.45,0) 2(0.45,0)
  body extent -0.5,-0.25 0.5,0.25, height 0.6
R1206_VISHAY_WSL1206 [mm] "WSL12065L000FEA18"
  rrect20% 1.6x1.8 smd mask+0.051: 1(-1.18,0) 2(1.18,0)
  body extent -1.6,-0.8 1.6,0.8, height 0.6
SOD323_2.5x1.25 [mm] "ON_Semi NSR0240H"
  rrect20% 0.63x0.83 smd: 1(-1.115,0) 2(1.115,0)
  body extent -1.21,-0.7 1.21,0.7, height 1.15
SOT553_L [mm] "SOT553 (_M050_W1.2_), 5-Leads, Body 1.60x1.20mm, Pitch 0.5mm, IPC High Density"
  rrect25% 0.6x0.3 smd: 1(-0.65,0.5) 2(-0.65,0) 3(-0.65,-0.5) 4(0.65,-0.5) 5(0.65,0.5)
  body extent -0.65,-0.85 0.65,0.85, height 0.6
SOT886 [mm] "SOT886 (170123)"
  rrect20% 0.325x0.27 smd paste+0 mask+0.051: 1(-0.337,0.5) 2(-0.337,0) 3(-0.337,-0.5) 4(0.337,-0.5) 5(0.337,0) 6(0.337,0.5)
  body extent -0.67,-0.9 0.67,0.9, height 0.5
SWITCH_CK_PTS810 [mm] "Switch, C&K, PTS810 H: 2.5 (170127)"
  rrect20% 1.05x0.65 smd: 1(-2.075,1.075) 2(2.075,1.075) 3(-2.075,-1.075) 4(2.075,-1.075)
  body extent -2.1,-1.63 2.1,1.63, height 2.6
TAG_CONN_TC2050-NL [mil] "Tag Connect TC2050-IDC-NL Land Pattern"
  round 30.98 smd paste-30.98: 1(-100,-25) 2(-50,-25) 3(0,-25) 4(50,-25) 5(100,-25) 6(100,25) 7(50,25) 8(0,25) 9(-50,25) 10(-100,25)
  round 0 hole 39 unplated mask+22: M1(-150,0) M2(150,40) M3(150,-40)
TDFN8_M050_2.0X3.0_EP [mm] "TDFN8_M050_2.0x3.0_EP"
  rrect20% 0.75x0.3 smd mask+0.051: 1(-1.45,0.75) 2(-1.45,0.25) 3(-1.45,-0.25) 4(-1.45,-0.75) 5(1.45,-0.75) 6(1.45,-0.25) 7(1.45,0.25) 8(1.45,0.75)
  rect 1.5x1.4 smd mask+0.051: 9(0,0)
  body extent -1.5,-1 1.5,1, height 1.01
TP_1.0_SMD#1 [mm] "Test Point, 1.0 mm, SMD"
  round 1 smd paste-0.501: 1(0,0)
TP_1.0_SMD#2 [mm] "Test Point, 1.0 mm, SMD"
  round 0.762 smd paste-0.501: 1(0,0)
WDFN8_M065_3.3X3.3_ONSEMI [mm] "WDFN8_M065_3.3x3.3_ONSEMI"
  rrect20% 0.42x0.66 smd mask+0.051: 1(0.975,1.47) 2(0.325,1.47) 3(-0.325,1.47) 4(-0.975,1.47) 5(-0.975,-1.47) 6(-0.325,-1.47) 7(0.325,-1.47) 8(0.975,-1.47)
  Top Layer region: 1.175,0.325 1.175,0.5 -1.175,0.5 -1.175,0.325 -1.75,0.325 -1.75,-0.25 -1.175,-0.25 -1.175,-1.325 1.175,-1.325 1.175,-0.25 1.75,-0.25 1.75,0.325
  body extent -1.7,-1.7 1.7,1.7, height 1
WE_632723_USB-C_RCPT [mm] "USB 3.1_Type C_Horizontal_THT/SMT_1.0mm (170208)"
  oval 1x1.6 on Top Paste: 0(-4.27,-4.73) 0(-4.27,0) 0(4.27,-4.73) 0(4.27,0)
  round 0.65 on Top Paste: 0(-2.8,1.14) 0(-2.4,0.44) 0(-2,1.14) 0(-1.6,0.44) 0(-1.2,1.14) 0(-0.8,0.44) 0(-0.4,1.14) 0(0.4,1.14) 0(0.8,0.44) 0(1.2,1.14) 0(1.6,0.44) 0(2,1.14) 0(2.4,0.44) 0(2.8,1.14)
  oval 1x1.6 hole 0.45 slot 0.85 at 90 deg paste+0: 25(-4.27,-4.73) 26(4.27,-4.73) 28(4.27,0)
  oval 1x1.6 hole 0.45 slot 0.85 at 90 deg paste-1: 27(-4.27,0)
  rect 0.2x1 smd: 29(0,-2.18) 30(0,-5.28)
  rrect10% 0.3x1.2 smd: A1(-2.75,2.4) A2(-2.25,2.4) A3(-1.75,2.4) A4(-1.25,2.4) A5(-0.75,2.4) A6(-0.25,2.4) A7(0.25,2.4) A8(0.75,2.4) A9(1.25,2.4) A10(1.75,2.4) A11(2.25,2.4) A12(2.75,2.4)
  round 0.65 hole 0.4 paste+0: B1(2.8,1.14) B2(2.4,0.44) B3(1.6,0.44) B4(1.2,1.14) B5(0.8,0.44) B6(0.4,1.14) B7(-0.4,1.14) B8(-0.8,0.44) B9(-1.2,1.14) B10(-1.6,0.44) B11(-2.4,0.44) B12(-2.8,1.14) GND(-2,1.14) GND(2,1.14)
  body extent -4.4,-9.1 4.34,2.69, height 3.08
WSON8_M050_2.5X3.0_HEAT [mm] "WSON8, Pitch 0.5, 3.0x2.5x0.8 EP TI: NGM"
  rrect20% 0.5x0.25 smd mask+0.051: 1(-1.15,0.75) 2(-1.15,0.25) 3(-1.15,-0.25) 4(-1.15,-0.75) 5(1.15,-0.75) 6(1.15,-0.25) 7(1.15,0.25) 8(1.15,0.75)
  rrect10% 1.2x1.5 smd mask+0.051: 9(0,0)
  body extent -1.5,-1.25 1.5,1.25, height 0.8
X_SSS_DSX211SH_2.05X1.65-4 [mm] "X_SSS_DSX211SH_2.05X1.65-4"
  rrect20% 0.9x0.8 smd mask+0.051: 1(-0.7,-0.55) 2(0.7,-0.55) 3(0.7,0.55) 4(-0.7,0.55)
  body extent -1.07,-0.87 1.07,0.87, height 0.51

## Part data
J1 J2: library part 1X18_2.54MM, "1X18_2.54MM"
P1: library part USB-C_RECEPTACLE, "USB-C_RECEPTACLE"
P900: library part USB_MICRO-B, "USB_MICRO-B"
X900: library part 48_MHz, "48_MHz"

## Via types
v1: diameter 0.5, hole 0.25, Top Layer to Bottom Layer, tented both sides, 369 vias
v2: diameter 0.762, hole 0.381, Top Layer to Bottom Layer, tented both sides, 21 vias

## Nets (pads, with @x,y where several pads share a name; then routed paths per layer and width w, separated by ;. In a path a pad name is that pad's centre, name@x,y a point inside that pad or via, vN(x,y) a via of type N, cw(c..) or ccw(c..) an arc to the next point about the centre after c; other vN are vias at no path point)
5V: C215.2 D901.2 J2.1 R209.2 U200.30 | length 90.6
  Top Layer w0.2: U200.30@21.85,34.34 21.85,34.85 21.7,35 21.7,35.65 21.825,35.525 R209.2@22.4,35.525
  Signal Layer 3 w0.5: v1(7.5,41.1) 7.525,41.075 11.525,41.075 17.6,35 v1@21.7,35
  Bottom Layer w0.2: 3.6,40.4 3.288,40.088 3.288,15.562 3.55,15.3 3.55,14.65 3.3,14.4 3.3,3.5 6.15,0.65 21.077,0.65 21.975,1.548 D901.2@21.975,2.2
  Bottom Layer w0.5: J2.1@4.853,49.34 3.6,48.087 3.6,40.4 6.8,40.4 v1(7.5,41.1)
  other v1: 21.75,35
BOARD_ID_SCL: R905.1 TPJ14.1 U900.38 U901.6 | length 51.2
  Signal Layer 3 w0.125: v1(16.4,6.4) 16.8,6 v1(16.8,5.2) 16.8,4.6 v1(17.6,3.8) ; v1(22.9,6.9) 26.95,10.95 29.85,10.95 30.9,12 32.995,12 34.75,13.755 34.75,20.631 35.838,21.719 35.838,21.822 35.85,21.834 ; v1(31.7,30.7) 33.897,30.7 35.9,28.696 35.9,21.834 35.875,21.809
  Bottom Layer w0.125: U900.38@15.55,8.375 15.55,8.07 15.938,7.682 15.938,6.862 v1(16.4,6.4) ; R905.1@16.175,5.1 16.275,5.2 v1(16.8,5.2) 17.5,5.2 U901.6@17.55,5.25 ; v1(17.6,3.8) 17.95,3.45 21.769,3.45 22.24,3.922 22.24,6.24 v1(22.9,6.9)
  Bottom Layer w0.2: TPJ14.1@30.75,30.8 30.85,30.7 v1(31.7,30.7)
BOARD_ID_SDA: R904.1 TPJ15.1 U900.37 U901.5 | length 55
  Signal Layer 3 w0.125: v1(15.9,3.9) 15.962,3.962 15.962,7.003 v1(16.46,7.5) ; v1(23.4,6) 23.4,6.65 27.384,10.634 30.283,10.634 31.35,11.701 33.05,11.701 35,13.651 35,20.35 36.3,21.65 36.3,28.65 33.75,31.2 v1(33.4,31.2)
  Bottom Layer w0.125: U900.37@16.05,8.375 16.05,8.07 16.46,7.66 v1(16.46,7.5) ; R904.1@16.175,4.5 R904.1@16.2,4.5 ; U901.5@17.55,4.75 16.75,4.75 16.5,4.5 R904.1@16.2,4.5 ; v1(23.4,6) 22.646,5.246 22.646,3.974 21.82,3.148 16.652,3.148 v1(15.9,3.9) 16.2,4.2 R904.1@16.2,4.5 ; TPJ15.1@30.75,33.4 32.05,32.1 32.5,32.1 v1(33.4,31.2)
BOARD_ID_WP: R906.1 TPJ16.1 U900.41 U901.7 | length 39
  Signal Layer 3 w0.125: v1(23.8,5.45) 23.15,5.45 22.25,6.35 22.25,16.35 23.3,17.4 25.05,17.4 26.1,18.45 26.85,18.45 v1(27.8,19.4)
  Bottom Layer w0.125: U900.41@14.05,8.375 14.05,7.905 13.8,7.655 13.8,7.219 13.837,7.181 13.837,6.819 13.8,6.781 13.8,5.632 14.482,4.95 ; R906.1@15,5.5 15.3,5.8 U901.7@17.6,5.8 ; R906.1@15,5.525 14.482,5.007 14.482,4.95 ; v1(23.8,5.45) 23.062,4.713 23.062,4.037 21.923,2.898 16.521,2.898 16.181,3.237 15.144,3.237 14.812,3.569 14.812,4.619 14.482,4.95 ; v1@27.95,19.35 TPJ16.1@28.65,19.35
BTN_RESET: BTN900.1 BTN900.2 C913.1 R915.2 R916.2 | length 19.4
  Top Layer w0.125: R915.2@10.575,15.275 C913.1@11.275,15.275 ; BTN900.2@11.375,9.925 BTN900.1@11.375,14.075 11.375,15.175 C913.1@11.275,15.275 ; R916.2@22.7,19.075 22.012,18.387 22.012,18.298 21.714,18 19.6,18 19.05,17.45 13.075,17.45 11.275,15.65 C913.1@11.275,15.275
DBG_3V3: C904.1 C910.1 C911.1 R904.2 R905.2 R906.2 R907.2 U900.46 U901.8 U902.A1 U902.E3 | length 44.3
  Signal Layer 3 w0.3: v1(8.55,17.8) 7.2,16.45 v1(7.2,15.2) 8.4,15.2 8.7,14.9 8.7,13.976 7.6,12.876 7.6,4.534 8.534,3.6 10.7,3.6 v1(12.7,5.6) 12.9,5.8 13.009,5.8 13.034,5.775 13.517,5.775 13.525,5.775 14.08,5.22 14.335,5.22 15.25,4.306 v1(15.25,3.75) 15.25,3.65 15.8,3.1 18.066,3.1 18.4,3.434 18.4,5.55 v1(16.95,7)
  Bottom Layer w0.125: U902.E3@7.1,16.5 7.1,15.3 v1(7.2,15.2) ; C904.1@11.7,7.275 11.976,7.275 12.7,6.551 v1(12.7,5.6)
  Bottom Layer w0.25: U902.A1@7.8,17.3 8.05,17.55 C911.1@8.05,18.225 ; C911.1@8.025,18.225 C911.1@8.05,18.225 ; R907.2@8.05,18.825 C911.1@8.05,18.225 ; v1(8.55,17.8) 8.55,18 8.325,18.225 C911.1@8.05,18.225 ; U900.46@11.55,8.375 11.55,7.425 C904.1@11.7,7.275 ; R906.2@15,4.9 15.2,4.7 15.2,4.5 ; v1(15.25,3.75) 15.25,4.45 15.2,4.5 ; R905.2@15.6,5.1 R904.2@15.6,4.5 ; R904.2@15.625,4.5 R904.2@15.6,4.5 ; v1(16.95,7) C910.1@17.425,7 17.425,6.375 U901.8@17.55,6.25 ; 15.2,4.5 R904.2@15.6,4.5
DBG_C2CK: J1.18 R916.1 U1.4 U900.2 | length 40.3
  Top Layer w0.125: U1.4@22,20.85 22,20.568 22.45,20.118 22.45,19.9 22.7,19.65 R916.1@22.7,19.625 23.058,19.267 23.058,18.808 22.8,18.55 22.531,18.55 22.262,18.281 22.262,17.812 v1(22.15,17.7)
  Signal Layer 3 w0.125: J1.18@2.313,6.16 3.373,5.1 5.5,5.1 5.9,5.5 5.9,12.412 6.4,12.912 6.4,15.48 6.541,15.621 6.541,16.771 7.332,17.562 7.335,17.562 8.572,18.8 v1(11.65,18.8) 13.6,18.8 14.95,17.45 19.116,17.45 20.716,19.05 21.619,19.05 21.987,18.681 v1@21.987,17.787
  Bottom Layer w0.125: U900.2@11.05,17.125 11.05,18.2 v1(11.65,18.8)
DBG_C2D: J2.18 U1.5 U900.1 | length 37.8
  Top Layer w0.125: U1.5@22.4,20.85 22.4,20.522 23.308,19.614 23.308,18.704 22.704,18.1 v1(22.7,18.1)
  Signal Layer 3 w0.125: J2.18@4.853,6.16 3.9,7.113 3.9,12.2 4.292,12.592 5.345,12.592 6.15,13.398 6.15,15.584 6.291,15.725 6.291,16.875 7.228,17.812 7.231,17.812 8.669,19.25 v1(11.15,19.25) 11.162,19.238 14.481,19.238 16.019,17.7 19.012,17.7 20.612,19.3 21.722,19.3 22.237,18.785 22.237,18.611 22.7,18.148 v1(22.7,18.1)
  Bottom Layer w0.125: U900.1@10.55,17.125 10.55,18.054 11.15,18.654 v1(11.15,19.25)
DBG_PGOOD: R912.2 R913.1 U900.7 U903.1 | length 30.7
  Signal Layer 3 w0.125: v1(12.4,18.1) 12.162,18.338 8.463,18.338 7.438,17.312 7.435,17.312 6.791,16.668 6.791,15.517 6.662,15.389 6.662,13.869 7.262,13.269 7.262,4.395 7.55,4.107 7.55,4.05 8.5,3.1 11.4,3.1 11.662,3.363 13.888,3.363 v1(13.9,3.35)
  Bottom Layer w0.125: U903.1@11.538,3.975 R912.2@12.937,3.975 ; v1(12.4,18.1) 12.762,17.738 13.243,17.738 13.55,17.43 U900.7@13.55,17.125 ; R912.2@12.9,3.95 13.25,3.95 13.85,3.35 v1(13.9,3.35)
DBG_RESET: U900.4
DBG_VBUS: C903.1 D902.2 L900.2 R908.2 TPJ12.1 U900.45 U900.52 | length 97.8
  Signal Layer 3 w0.3: v1@8.2,41.7 12,41.7 14.7,39 21.557,39 22.832,37.725 23.575,37.725 24.075,37.225 25.825,37.225 27.05,36 v1(29.6,36) v1@29.6,36.107
  Signal Layer 3 w0.5: v1(9.092,10.958) 8.75,10.616 v1(8.75,8.1) 11.416,8.1 12.775,6.741 13.141,6.375 13.176,6.375 13.251,6.3 v1(13.3,6.3)
  Bottom Layer w0.125: C903.1@12.425,7.4 12.425,7.356 13.219,6.562 13.247,6.562 13.3,6.509 v1(13.3,6.3)
  Bottom Layer w0.2: 11,1.3 11.025,1.325 R908.2@11.025,2.175
  Bottom Layer w0.25: U900.45@12.05,8.375 12.05,7.775 C903.1@12.425,7.4
  Bottom Layer w0.3: v1@8.2,41.7 8.2,40.858 5.242,37.9 4.6,37.9 3.7,37 3.7,15.895 3.965,15.63 3.965,14.535 3.7,14.27 3.7,8.1 4.4,7.4 6.3,7.4 7,8.1 v1(8.75,8.1) ; v1@29.55,36.05 TPJ12.1@30.35,36.05
  Bottom Layer w0.305: v1(9.092,10.958) 9.092,10.75 9.342,10.5 U900.52@9.925,10.5
  Bottom Layer w0.5: v1(8.75,8.1) 8.75,7.3 ; L900.2@9.6,7.28 9.58,7.3 8.75,7.3 ; D902.2@18.625,2.2 16.6,2.2 16,2.8 14.6,2.8 13.1,1.3 11,1.3 10,1.3 7.723,3.577 7.723,5.023 8.75,6.05 8.75,7.3
  other v1: 8.1,41.7
DBGMCU_LED: R902.1 U900.21 | length 2
  Bottom Layer w0.125: U900.21@18.675,14.5 18.98,14.5 19.88,15.4 R902.1@20.325,15.4
DBGMCU_RESET: P901.3 TPJ17.1 U900.20 | length 55.7
  Top Layer w0.125: v1(17.4,20.15) 19,18.55 v1(19,18.4)
  Signal Layer 3 w0.125: v1@7.8,27.4 17.85,27.4 v1(18.25,27)
  Bottom Layer w0.125: P901.3@4.86,52.23 5.39,51.7 5.39,51.06 8.2,48.25 8.2,42.926 9.4,41.726 9.4,40.219 8.2,39.019 8.2,37.454 7.8,37.054 7.8,27.6 v1(7.6,27.4) ; v1(17.4,20.15) 17.312,20.062 16.319,20.062 15.75,20.631 15.75,24.504 v1@18.146,26.9 ; v1(18.25,27) 19.25,27 TPJ17.1@19.95,27.7 ; U900.20@18.675,15 19,15 19.4,15.4 19.4,18.003 19,18.403 v1(19,18.4)
DBGMCU_RXD: P901.4 TPJ6.1 U900.63 | length 62.1
  Signal Layer 3 w0.125: v1@8.9,40.5 11.45,40.5 17.6,34.35 v1(24.9,34.35)
  Bottom Layer w0.125: P901.4@3.59,52.23 4.22,51.6 4.45,51.6 7.9,48.15 7.9,42.872 8.95,41.822 v1(8.95,40.4) 7.875,39.325 7.875,37.482 7.55,37.157 7.55,28.4 7.15,28 7.15,23.443 9.55,21.043 9.55,17.3 9.3,17.05 9.3,16.32 9.62,16 U900.63@9.925,16 ; TPJ6.1@23.42,32.67 23.7,32.95 23.7,33.8 24.25,34.35 v1(24.9,34.35)
DBGMCU_SPI_CS: R907.1 U900.61 U902.A3 | length 8.6
  Bottom Layer w0.125: U902.A3@7.1,17.3 6.612,17.788 6.612,18.454 6.983,18.825 R907.1@7.475,18.825 7.85,19.2 8.325,19.2 8.988,18.537 8.988,17.491 8.8,17.304 8.8,15.8 9.6,15 U900.61@9.925,15
DBGMCU_SPI_MISO: U900.59 U902.C3 | length 6.2
  Signal Layer 3 w0.125: v1(7.1,14.3) 7.8,14.3 v1(8.1,14.6)
  Bottom Layer w0.125: v1(7.1,14.3) 7,14.3 6.736,14.564 6.736,16.55 7.086,16.9 U902.C3@7.1,16.9 ; v1(8.1,14.6) 8.1,14.5 8.6,14 U900.59@9.925,14
DBGMCU_SPI_MOSI: U900.58 U902.D2 | length 5
  Bottom Layer w0.125: U902.D2@7.45,16.7 7.45,15.6 7.662,15.388 7.662,14.363 8.525,13.5 U900.58@9.925,13.5
DBGMCU_SPI_SCLK: U900.60 U902.E1 | length 3.4
  Bottom Layer w0.125: U902.E1@7.8,16.5 7.8,15.681 8.981,14.5 U900.60@9.925,14.5
DBGMCU_SWCLK: P901.8 TPJ2.1 U900.49 | length 76
  Signal Layer 3 w0.125: v1(7.05,38.35) 8.25,38.35 v1(8.7,38.8) 9.225,39.325 11.106,39.325 14.475,35.956 v1(14.475,35.15)
  Bottom Layer w0.125: P901.8@4.86,53.5 5.497,54.137 9.192,54.137 10.3,53.029 10.3,51.95 8.5,50.15 8.5,42.979 9.65,41.829 9.65,39.85 8.7,38.9 v1(8.7,38.8) ; v1(7.05,38.35) 7.05,31.55 6.65,31.15 6.65,23.236 8.75,21.136 8.75,20.65 8.238,20.138 6.719,20.138 5.862,19.281 5.862,10.48 7.343,9 U900.49@9.925,9 ; v1(14.475,35.15) 14.563,35.238 18.538,35.238 19,35.7 20.975,35.7 21.195,35.48 TPJ2.1@22.5,35.48
DBGMCU_SWDIO: P901.7 TPJ1.1 U900.50 | length 73.8
  Signal Layer 3 w0.125: v1(6.9,19.7) 7.338,20.138 9.838,20.138 v1(10.3,20.6) 10.312,20.588 14.266,20.588 16.004,18.85 19.45,18.85 v1(19.5,18.9)
  Bottom Layer w0.125: P901.7@3.59,53.5 4.49,54.4 9.396,54.4 10.55,53.246 10.55,51.846 8.8,50.096 8.8,43.1 9.9,42 9.9,39.381 8.45,37.931 8.45,37.35 8.05,36.95 8.05,26.85 7.85,26.65 7.85,23.096 10.3,20.646 v1(10.3,20.6) ; v1(6.9,19.7) 6.112,18.912 6.112,10.584 7.196,9.5 U900.50@9.925,9.5 ; v1(19.5,18.9) 20.4,18.9 20.9,19.4 22.1,19.4 TPJ1.1@22.15,19.35
DBGMCU_SWO: P901.6 TPJ3.1 U900.51 | length 77.1
  Signal Layer 3 w0.125: v1(7.75,19.7) 7.8,19.75 10.4,19.75 10.8,20.15 v1(11.65,20.15) 14.35,20.15 15.9,18.6 17.5,18.6 v1(17.8,18.3)
  Bottom Layer w0.125: P901.6@2.32,53.5 3.47,54.65 9.5,54.65 10.8,53.35 10.8,51.743 9.1,50.043 9.1,43.254 10.15,42.204 10.15,39.278 9,38.128 9,36.381 8.3,35.681 8.3,26.463 8.1,26.263 8.1,23.2 10.1,21.2 10.619,21.2 11.65,20.169 v1(11.65,20.15) ; 6.604,18.799 6.362,18.558 6.362,10.688 7.05,10 U900.51@9.925,10 ; 6.604,18.8 7.066,19.262 7.312,19.262 v1(7.75,19.7) ; v1(17.8,18.3) 17.8,18.8 19.8,20.8 21,20.8 TPJ3.1@22.1,21.9
DBGMCU_TEST_MODE: TPJ11.1 U900.36 | length 37.2
  Signal Layer 3 w0.125: v1(22.8,8.3) 22.8,9.5 24.55,11.25 29.65,11.25 30.8,12.4 32.55,12.4 34.2,14.05 34.2,21.95 34.712,22.462 34.712,23.484 34.021,24.175 31.325,24.175 v1(31,23.85)
  Bottom Layer w0.125: U900.36@16.55,8.375 16.55,8.05 17.15,7.45 21.95,7.45 v1(22.8,8.3) ; v1(31,23.85) 31,23.7 TPJ11.1@31,25.35
DBGMCU_TXD: P901.5 TPJ5.1 U900.62 | length 56
  Signal Layer 3 w0.125: v1(7.1,30.3) 8.25,29.15 v1(18,29.15)
  Bottom Layer w0.125: P901.5@2.32,52.23 3.25,51.3 4.296,51.3 7.5,48.096 7.5,42.919 8.538,41.881 8.538,40.603 7.584,39.65 7.584,37.584 7.3,37.3 7.3,30.5 v1(7.1,30.3) 6.9,30.1 6.9,23.339 9.3,20.939 9.3,17.45 9.05,17.2 9.05,16.07 9.62,15.5 U900.62@9.925,15.5 ; v1(18,29.15) 18.8,29.15 TPJ5.1@19.95,30.3
DBGMCU_USB_DM: D900.4 P900.2 R900.1 | length 3
  Top Layer w0.125: D900.4@10.5,5.9 10.7,6.1 v1@10.985,6.1
  Top Layer w0.127: D900.4@10.5,5.85 10.5,5.216 10.845,4.871 P900.2@10.845,4.35
  Bottom Layer w0.125: v1(10.95,6.25) 10.95,6.675 R900.1@11.1,6.825 ; R900.1@10.985,6.735 R900.1@11.075,6.825
DBGMCU_USB_DP: D900.5 P900.3 R901.1 | length 4.5
  Top Layer w0.125: D900.5@11.5,5.85 D900.5@11.5,5.9 11.9,5.9 v1(12,5.8)
  Top Layer w0.127: P900.3@11.495,4.35 11.495,5.845 D900.5@11.5,5.85
  Bottom Layer w0.125: R901.1@10.525,6.825 10.494,6.794 10.494,6.088 10.769,5.812 11.988,5.812 v1(12,5.8)
DBGMCU_USB_SENSE: R908.1 R909.1 R912.1 U900.32 U903.3 | length 16.9
  Signal Layer 3 w0.125: v1(13.5,2.7) 13.8,2.7 18.9,2.7 19.7,3.5 v1(19.7,8.3)
  Bottom Layer w0.125: U903.3@11.538,2.975 11.538,2.138 11.6,2.075 12.775,2.075 R909.1@12.9,2.2 13.4,2.7 v1(13.5,2.7) 13.5,3.1 13.2,3.4 R912.1@12.9,3.4 ; U900.32@18.675,9 19,9 v1(19.7,8.3)
EFM8_P0.2: J1.3 U1.31 | length 36.6
  Top Layer w0.125: v1(15.25,24.25) 15.25,23.4 16.562,22.088 16.85,22.088 17.038,21.9 U1.31@20.15,21.9
  Signal Layer 3 w0.125: J1.3@2.313,44.26 3.573,43 5.15,43 5.791,42.359 5.791,36.059 7.038,34.812 7.038,32.151 8.638,30.55 v1(15.25,30.55)
  Bottom Layer w0.125: v1@15.175,30.575 15.2,30.55 v1(15.25,30.55) ; v1(15.25,24.25) v1(15.25,30.55) ; v1@15.25,30.575 v1(15.25,30.55)
EFM8_P0.3: J1.4 U1.30 | length 37.7
  Top Layer w0.125: v1(16.5,23.55) 17.75,22.3 U1.30@20.15,22.3
  Signal Layer 3 w0.125: J1.4@2.313,41.72 0.6,40.007 0.6,25.7 1.422,24.878 6.272,24.878 7.35,23.8 16.25,23.8 v1(16.5,23.55)
EFM8_P0.4: J1.5 U1.29 | length 34.5
  Top Layer w0.125: v1(16.5,24.25) 18.05,22.7 U1.29@20.15,22.7
  Signal Layer 3 w0.125: J1.5@2.313,39.18 0.85,37.717 0.85,25.95 1.672,25.128 15.622,25.128 v1(16.5,24.25)
EFM8_P0.5: J1.6 U1.28 | length 31.4
  Top Layer w0.125: v1(18.6,23.45) 19.1,22.95 19.743,22.95 19.893,23.1 U1.28@20.15,23.1
  Signal Layer 3 w0.125: J1.6@2.313,36.64 1.1,35.427 1.1,26.25 1.972,25.378 16.054,25.378 17.981,23.45 v1(18.6,23.45)
EFM8_P0.6: J1.7 U1.27 | length 25.5
  Top Layer w0.125: v1@19.3,23.5 U1.27@20.15,23.5
  Signal Layer 3 w0.125: J1.7@2.313,34.1 2.313,33.883 3.251,32.946 3.251,30.799 4.092,29.958 5.3,29.958 7.345,27.912 17.988,27.912 19.3,26.6 v1(19.3,23.45)
EFM8_P0.7: J1.8 R219.2 U1.26 U200.9 | length 35.4
  Top Layer w0.125: v1(19.9,28.85) 19.9,29.3 20.26,29.66 U200.9@20.85,29.66 ; R219.2@20.1,26.4 18.9,25.2 v1(17.9,25.2) 17.9,24.15 18.15,23.9 U1.26@20.15,23.9
  Signal Layer 3 w0.125: J1.8@2.313,31.56 1.375,30.622 1.375,28.632 2.25,27.757 5.443,27.757 6.65,26.55 16.55,26.55 v1(17.9,25.2)
  Bottom Layer w0.125: v1(17.9,25.2) 19.831,25.2 19.894,25.262 20.231,25.262 20.638,25.669 20.638,28.037 19.9,28.775 v1@19.9,28.9
EFM8_P1.0: J1.9 U1.25 | length 20.4
  Top Layer w0.125: v1(18.35,24.35) 18.4,24.3 U1.25@20.15,24.3
  Signal Layer 3 w0.125: J1.9@2.313,29.02 3.283,28.05 5.6,28.05 6.75,26.9 16.819,26.9 18.338,25.381 18.338,24.362 v1(18.35,24.35)
EFM8_P1.1: D2.4 P1.A5 R13.1 R917.2 R919.2 U1.9 U1.24 | length 40.5
  Top Layer w0.125: v1(20.05,24.8) 20.75,24.8 U1.24@20.8,24.85 ; v1(24.1,21.05) 24.25,21.2 U1.9@24.25,21.5 ; v1(24.6,6.8) 25,6.4 D2.4@25,6.2 R13.1@25,5.275 ; P1.A5@31.2,10.1 31.2,10.606 31.694,11.1 v1(31.7,11.1)
  Signal Layer 3 w0.125: v1(24.6,6.8) 24.649,6.8 28.049,10.2 30.8,10.2 v1(31.7,11.1)
  Bottom Layer w0.125: R919.2@19.475,24.2 R917.2@19.475,24.8 20.025,24.8 v1@20.05,24.825 ; v1(20.05,24.8) 21.694,24.8 22.638,25.744 22.638,26.206 23.169,26.738 23.531,26.738 23.788,26.481 23.788,25.469 23.625,25.306 23.625,24.094 24.1,23.619 v1(24.1,21.05) 23.2,20.15 23.2,17.904 22.7,17.404 22.7,9.117 24.6,7.217 v1(24.6,6.8)
EFM8_P1.2: D2.5 P1.B5 R21.1 R918.2 R920.2 U1.7 U1.23 | length 40
  Top Layer w0.125: v1(20.05,25.7) 20.731,25.7 21.2,25.231 U1.23@21.2,24.95 ; U1.7@23.2,20.85 23.2,20.45 23.525,20.125 23.675,20.125 v1(24,19.8) ; R21.1@26,5.275 D2.5@26,6.2 v1(26.7,6.2) 30.81,6.2 P1.B5@32.75,8.14
  Signal Layer 3 w0.125: v1(20.05,25.7) 21.062,26.712 21.581,26.712 21.934,27.066 22.416,27.066 22.888,26.594 22.888,25.64 22.762,25.515 22.762,23.688 24.638,21.812 24.638,20.219 24.219,19.8 v1(24,19.8)
  Bottom Layer w0.125: R920.2@19.475,26.2 19.475,25.65 19.5,25.625 v1@19.975,25.625 ; v1@23.9,19.8 23.45,19.35 23.45,17.8 23.05,17.4 23.05,9.431 24.431,8.05 24.869,8.05 26.7,6.219 v1(26.7,6.2)
EFM8_P1.3: J1.12 U1.22 | length 23.5
  Top Layer w0.125: v1@21,25.95 v1@21.026,25.924 ; v1@21.026,25.901 v1@21.026,25.924 ; U1.22@21.6,24.95 21.6,25.35 v1@21.026,25.924
  Signal Layer 3 w0.125: J1.12@2.313,21.4 3.665,22.752 5.411,22.752 5.959,23.3 15.4,23.3 16.3,22.4 18.869,22.4 20.488,24.019 20.488,25.338 v1(21.1,25.95)
EFM8_P1.4: J1.13 R220.2 U1.21 U200.10 | length 31.7
  Top Layer w0.125: v1(20.55,28.85) 20.681,28.85 21.35,29.519 U200.10@21.35,29.66 ; R220.2@20.7,26.4 21.5,26.4 v1(21.65,26.25) 21.65,25.775 22,25.425 U1.21@22,24.95
  Signal Layer 3 w0.125: J1.13@2.313,18.86 3.45,19.997 3.45,21.676 4.276,22.502 5.515,22.502 6.062,23.05 15.296,23.05 16.196,22.15 18.972,22.15 20.738,23.915 20.738,24.969 21.65,25.881 v1(21.65,26.25)
  Bottom Layer w0.125: v1(20.55,28.85) 20.888,28.512 20.888,27.012 v1(21.65,26.25)
EFM8_P1.5: J1.14 U1.20 | length 28.5
  Top Layer w0.125: v1(22.2,25.925) 22.4,25.725 U1.20@22.4,24.95
  Signal Layer 3 w0.125: J1.14@2.313,16.32 3.4,17.407 3.4,19.593 4.107,20.3 5.079,20.3 5.791,21.012 5.791,21.39 6.95,22.55 14.981,22.55 16.319,21.212 19.131,21.212 22.2,24.281 v1(22.2,25.925)
EFM8_P1.6: J1.15 U1.19 | length 32.9
  Top Layer w0.125: v1(22.2,26.6) 22.8,26 U1.19@22.8,24.95
  Signal Layer 3 w0.125: J1.15@2.3,13.8 2.3,14.95 3.665,16.315 3.665,19.448 4.267,20.05 5.265,20.05 6.112,20.897 6.112,21.292 7.121,22.3 14.878,22.3 16.215,20.962 19.262,20.962 22.45,24.15 22.45,25.556 22.638,25.744 22.638,26.162 v1(22.2,26.6) ; J1.15@2.313,13.78 J1.15@2.313,13.8
EFM8_P2.1: J2.5 R221.2 U1.16 U200.11 | length 38.5
  Top Layer w0.125: v1(21.3,28.85) 21.85,29.4 U200.11@21.85,29.66 ; R221.2@23.8,26.85 23.8,26.204 24.05,25.954 24.05,24.7 v1(24.075,24.675) 24.1,24.65 24.1,24.338 24.138,24.3 U1.16@24.25,24.3
  Signal Layer 3 w0.125: J2.5@4.853,39.18 3.85,38.177 3.85,33.777 4.465,33.162 4.588,33.162 6.524,31.226 6.524,30.226 8.05,28.7 19.431,28.7 19.719,28.412 20.862,28.412 v1(21.3,28.85)
  Bottom Layer w0.125: v1(21.3,28.85) 21.95,28.2 23.328,28.2 25.187,26.341 25.187,25.869 25.062,25.744 25.062,25.406 25.463,25.006 25.463,24.644 25.206,24.387 24.363,24.387 v1@24.1,24.65
EFM8_P2.2: J2.6 U1.15 | length 29.2
  Top Layer w0.125: U1.15@24.25,23.9 24.507,23.9 24.788,24.181 24.788,24.419 24.538,24.669 24.538,25.338 v1(24.6,25.4)
  Signal Layer 3 w0.125: J2.6@4.853,36.64 4.853,35.728 6.1,34.481 6.1,32.381 8.631,29.85 18.454,29.85 18.754,29.55 22.261,29.55 24.288,27.523 24.288,25.712 v1(24.6,25.4)
EFM8_P2.3: J2.7 R222.1 U1.14 | length 32.1
  Top Layer w0.125: U1.14@24.25,23.5 24.507,23.5 25.038,24.031 25.038,24.788 v1@25.05,24.8
  Signal Layer 3 w0.125: J2.7@4.853,34.1 5.814,33.139 5.814,32.314 8.528,29.6 18.35,29.6 18.65,29.3 22.157,29.3 24.038,27.42 24.038,25.344 24.55,24.831 25.019,24.831 v1(25.025,24.825)
  Bottom Layer w0.125: R222.1@22.5,27.8 23.022,27.8 24.038,26.785 24.038,25.344 24.556,24.825 v1(25.025,24.825) ; v1@25.025,24.8 v1@25.05,24.8
EFM8_P2.4: J2.8 R223.1 U1.13 | length 31.3
  Top Layer w0.125: U1.13@24.25,23.1 24.507,23.1 25.4,23.993 25.4,24.531 25.5,24.631 v1@25.5,25.7
  Signal Layer 3 w0.125: v1(6.6,32.5) 6.6,32.235 8.735,30.1 18.6,30.1 18.9,29.8 22.364,29.8 25.5,26.664 v1@25.5,25.6
  Bottom Layer w0.125: J2.8@4.853,31.56 5.793,32.5 v1(6.6,32.5) ; R223.1@23.8,28.3 23.819,28.3 25.5,26.619 v1@25.5,25.7
  other v1: 25.525,25.575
